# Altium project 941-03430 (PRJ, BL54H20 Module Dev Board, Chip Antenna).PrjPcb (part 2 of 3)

## Sheet CS-DOC-000013317[Debugger_MCU].SchDoc: =BoardTitle +' IMCU'
size OrCAD C; Organization: Nordic Semiconductor; DocumentNumber: 3; SheetNumber: 4; SheetTotal: 8; CompanyName: Nordic Semiconductor; DocumentSize: A4; SheetName: Debugger_MCU
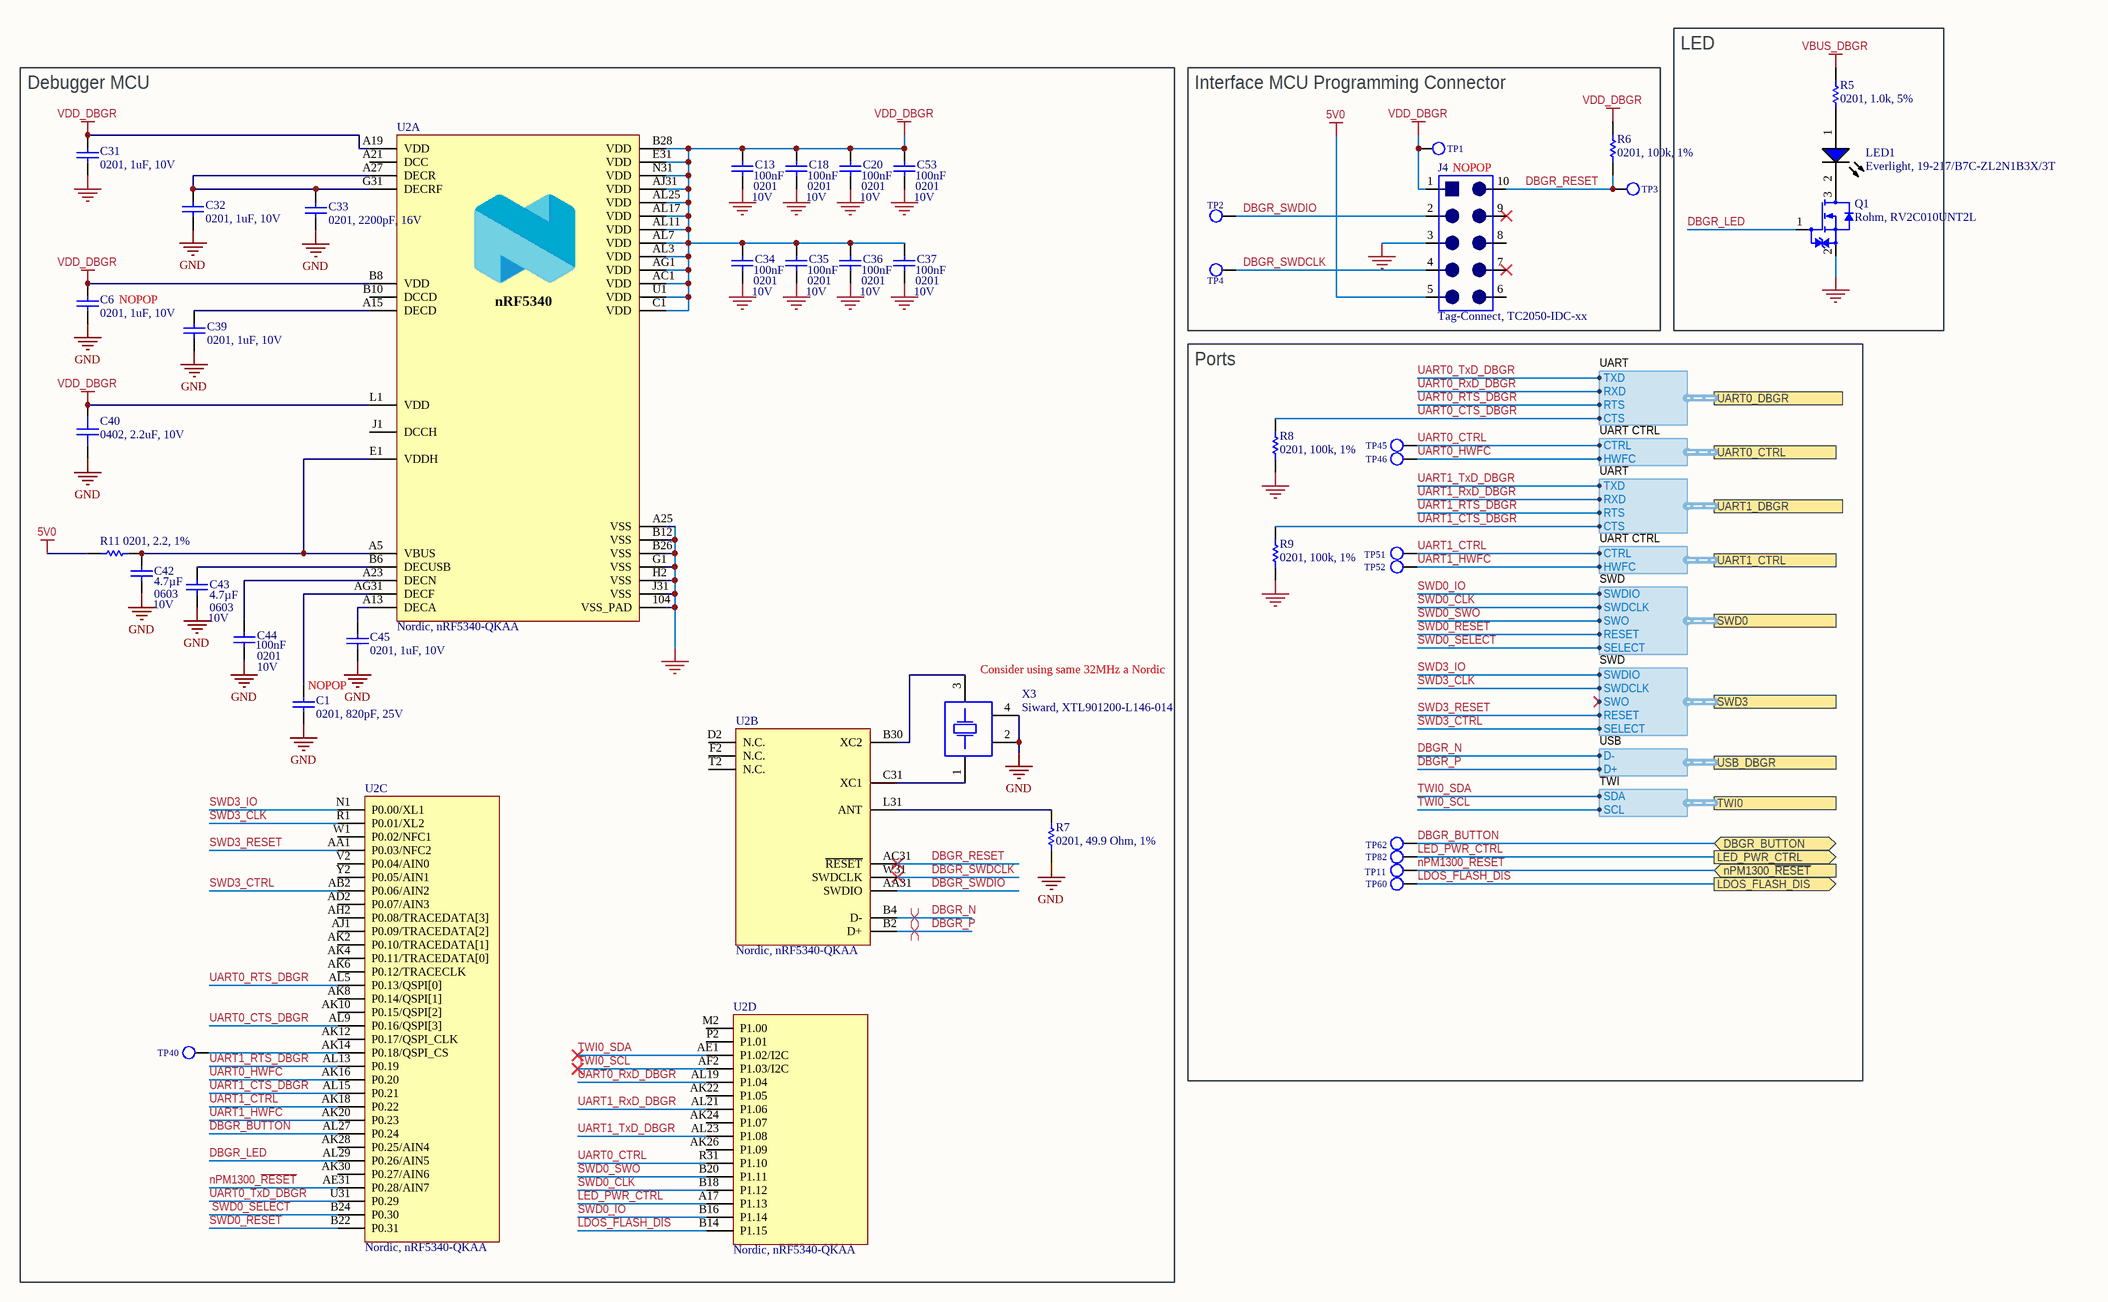
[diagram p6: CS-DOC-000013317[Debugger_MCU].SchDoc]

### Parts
C1  0201, 820pF, 25V  [Cap, C0201, Height 0.3mm]
C6  0201, 1uF, 10V  [Cap, C0201, Height 0.3mm]
C13  value 100nF  Footprint: 0201  Voltage: 10V  [Cap, C0201, Height 0.3mm]  (hidden comment: 0201, 100nF, 10V)
C18  value 100nF  Footprint: 0201  Voltage: 10V  [Cap, C0201, Height 0.3mm]  (hidden comment: 0201, 100nF, 10V)
C20  value 100nF  Footprint: 0201  Voltage: 10V  [Cap, C0201, Height 0.3mm]  (hidden comment: 0201, 100nF, 10V)
C31  0201, 1uF, 10V  [Cap, C0201, Height 0.3mm]
C32  0201, 1uF, 10V  [Cap, C0201, Height 0.3mm]
C33  0201, 2200pF, 16V  [Cap, C0201, Height 0.3mm]
C34  value 100nF  Footprint: 0201  Voltage: 10V  [Cap, C0201, Height 0.3mm]  (hidden comment: 0201, 100nF, 10V)
C35  value 100nF  Footprint: 0201  Voltage: 10V  [Cap, C0201, Height 0.3mm]  (hidden comment: 0201, 100nF, 10V)
C36  value 100nF  Footprint: 0201  Voltage: 10V  [Cap, C0201, Height 0.3mm]  (hidden comment: 0201, 100nF, 10V)
C37  value 100nF  Footprint: 0201  Voltage: 10V  [Cap, C0201, Height 0.3mm]  (hidden comment: 0201, 100nF, 10V)
C39  0201, 1uF, 10V  [Cap, C0201, Height 0.3mm]
C40  0402, 2.2uF, 10V  [Chip. 0402, RF]
C42  value 4.7µF  Footprint: 0603  Voltage: 10V  [Chip, 0603, RF]  (hidden comment: 0603, 4.7µF, 10V)
C43  value 4.7µF  Footprint: 0603  Voltage: 10V  [Chip, 0603, RF]  (hidden comment: 0603, 4.7µF, 10V)
C44  value 100nF  Footprint: 0201  Voltage: 10V  [Cap, C0201, Height 0.3mm]  (hidden comment: 0201, 100nF, 10V)
C45  0201, 1uF, 10V  [Cap, C0201, Height 0.3mm]
C53  value 100nF  Footprint: 0201  Voltage: 10V  [Cap, C0201, Height 0.3mm]  (hidden comment: 0201, 100nF, 10V)
J4  Tag-Connect, TC2050-IDC-xx  [TC2050-NL, TAG Test Interface]  (no BOM)
LED1  Everlight, 19-217/B7C-ZL2N1B3X/3T  [Everlight, LED0603, Blue]
Q1  Rohm, RV2C010UNT2L  [DFN1006-3]
R5  0201, 1.0k, 5%  [RES, R0201, Height 0.23mm]
R6  0201, 100k, 1%  [RES, R0201, Height 0.23mm]
R7  0201, 49.9 Ohm, 1%  [RES, R0201, Height 0.23mm]
R8  0201, 100k, 1%  [RES, R0201, Height 0.23mm]
R9  0201, 100k, 1%  [RES, R0201, Height 0.23mm]
R11  0201, 2.2, 1%  [RES, R0201, Height 0.23mm]
TP1  SMT, 1.5mm, Test Pad  [Test Point, SMT 1.5mm Round]  (value not drawn)  (no BOM)
TP2  SMT, 1.5mm, Test Pad  [Test Point, SMT 1.5mm Round]  (value not drawn)  (no BOM)
TP3  SMT, 1.5mm, Test Pad  [Test Point, SMT 1.5mm Round]  (value not drawn)  (no BOM)
TP4  SMT, 1.5mm, Test Pad  [Test Point, SMT 1.5mm Round]  (value not drawn)  (no BOM)
TP11  SMT, 1.5mm, Test Pad  [Test Point, SMT 1.5mm Round]  (value not drawn)  (no BOM)
TP40  SMT, 1.5mm, Test Pad  [Test Point, SMT 1.5mm Round]  (value not drawn)  (no BOM)
TP45  SMT, 1.5mm, Test Pad  [Test Point, SMT 1.5mm Round]  (value not drawn)  (no BOM)
TP46  SMT, 1.5mm, Test Pad  [Test Point, SMT 1.5mm Round]  (value not drawn)  (no BOM)
TP51  SMT, 1.5mm, Test Pad  [Test Point, SMT 1.5mm Round]  (value not drawn)  (no BOM)
TP52  SMT, 1.5mm, Test Pad  [Test Point, SMT 1.5mm Round]  (value not drawn)  (no BOM)
TP60  SMT, 1.5mm, Test Pad  [Test Point, SMT 1.5mm Round]  (value not drawn)  (no BOM)
TP62  SMT, 1.5mm, Test Pad  [Test Point, SMT 1.5mm Round]  (value not drawn)  (no BOM)
TP82  SMT, 1.5mm, Test Pad  [Test Point, SMT 1.5mm Round]  (value not drawn)  (no BOM)
U2  Nordic, nRF5340-QKAA  [Nordic, nRF5340-QKAA]  (parts A,B,C,D of 4)
X3  Siward, XTL901200-L146-014  [Crystal, 4 pin, 1.6mm x 1.2mm]

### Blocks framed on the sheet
LED: LED1 Q1 R5
Debugger MCU: C1 C6 C13 C18 C20 C31-C37 C39 C40 C42-C45 C53 R7 R11 TP40 U2 X3
Interface MCU Programming Connector: J4 R6 TP1-TP4
Ports: R8 R9 TP11 TP45 TP46 TP51 TP52 TP60 TP62 TP82

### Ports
DBGR_BUTTON (bidir), LDOS_FLASH_DIS (out), LED_PWR_CTRL (out), nPM1300_~{RESET} (in), SWD0 (harness SWD), SWD3 (harness SWD), TWI0 (harness TWI), UART0_CTRL (harness UART CTRL), UART0_DBGR (harness UART), UART1_CTRL (harness UART CTRL), UART1_DBGR (harness UART), USB_DBGR (harness USB)

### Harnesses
SWD: SWDIO, SWDCLK, SWO, RESET, SELECT
UART: RTS, CTS, RXD, TXD
USB: D+, D-
TWI: SCL, SDA
UART CTRL: HWFC, CTRL

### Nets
5V0: J4.5 R11.1
GND: C1.2 C6.2 C13.2 C18.2 C20.2 C31.2 C32.2 C33.2 C34.2 C35.2 C36.2 C37.2 C39.2 C40.2 C42.2 C43.2 C44.2 C45.2 C53.2 J4.3 Q1.2(S) R7.2 R8.2 R9.2 U2.104(VSS_PAD) U2.A25(VSS) U2.B12(VSS) U2.B26(VSS) U2.G1(VSS) U2.H2(VSS) U2.J31(VSS) X3.2 X3.4
VBUS_DBGR: R5.2
VDD_DBGR: C6.1 C13.1 C18.1 C20.1 C31.1 C34.1 C35.1 C36.1 C37.1 C40.1 C53.1 J4.1 R6.2 TP1.1 U2.A19(VDD) U2.AC1(VDD) U2.AG1(VDD) U2.AJ31(VDD) U2.AL3(VDD) U2.AL7(VDD) U2.AL11(VDD) U2.AL17(VDD) U2.AL25(VDD) U2.B8(VDD) U2.B28(VDD) U2.C1(VDD) U2.E31(VDD) U2.L1(VDD) U2.N31(VDD) U2.U1(VDD)
DBGR_BUTTON: TP62.1 U2.AL27(P0.24) ; port DBGR_BUTTON
DBGR_LED: Q1.1(G) U2.AL29(P0.26/AIN5)
DBGR_N: U2.B4(D-) ; port USB_DBGR.D-
DBGR_P: U2.B2(D+) ; port USB_DBGR.D+
DBGR_RESET: J4.10 R6.1 TP3.1 U2.AC31(~{RESET})
DBGR_SWDCLK: J4.4 TP4.1 U2.W31(SWDCLK)
DBGR_SWDIO: J4.2 TP2.1 U2.AA31(SWDIO)
LDOS_FLASH_DIS: TP60.1 U2.B14(P1.15) ; port LDOS_FLASH_DIS
LED_PWR_CTRL: TP82.1 U2.A17(P1.13) ; port LED_PWR_CTRL
nPM1300_~{RESET}: TP11.1 U2.AE31(P0.28/AIN7) ; port nPM1300_~{RESET}
SWD0_CLK: U2.B18(P1.12) ; port SWD0.SWDCLK
SWD0_IO: U2.B16(P1.14) ; port SWD0.SWDIO
SWD0_RESET: U2.B22(P0.31) ; port SWD0.RESET
SWD0_SELECT: U2.B24(P0.30) ; port SWD0.SELECT
SWD0_SWO: U2.B20(P1.11) ; port SWD0.SWO
SWD3_CLK: U2.R1(P0.01/XL2) ; port SWD3.SWDCLK
SWD3_CTRL: U2.AB2(P0.06/AIN2) ; port SWD3.SELECT
SWD3_IO: U2.N1(P0.00/XL1) ; port SWD3.SWDIO
SWD3_RESET: U2.AA1(P0.03/NFC2) ; port SWD3.RESET
TWI0_SCL: U2.AF2(P1.03/I2C) ; port TWI0.SCL
TWI0_SDA: U2.AE1(P1.02/I2C) ; port TWI0.SDA
UART0_CTRL: TP45.1 U2.R31(P1.10) ; port UART0_CTRL.CTRL
UART0_CTS_DBGR: R8.1 U2.AL9(P0.16/QSPI[3]) ; port UART0_DBGR.CTS
UART0_HWFC: TP46.1 U2.AK16(P0.20) ; port UART0_CTRL.HWFC
UART0_RTS_DBGR: U2.AL5(P0.13/QSPI[0]) ; port UART0_DBGR.RTS
UART0_RxD_DBGR: U2.AL19(P1.04) ; port UART0_DBGR.RXD
UART0_TxD_DBGR: U2.U31(P0.29) ; port UART0_DBGR.TXD
UART1_CTRL: TP51.1 U2.AK18(P0.22) ; port UART1_CTRL.CTRL
UART1_CTS_DBGR: R9.1 U2.AL15(P0.21) ; port UART1_DBGR.CTS
UART1_HWFC: TP52.1 U2.AK20(P0.23) ; port UART1_CTRL.HWFC
UART1_RTS_DBGR: U2.AL13(P0.19) ; port UART1_DBGR.RTS
UART1_RxD_DBGR: U2.AL21(P1.06) ; port UART1_DBGR.RXD
UART1_TxD_DBGR: U2.AL23(P1.08) ; port UART1_DBGR.TXD
NetC1_1: C1.1 U2.AG31(DECF)
NetC32_1: C32.1 C33.1 U2.A27(DECR) U2.G31(DECRF)
NetC39_1: C39.1 U2.A15(DECD)
NetC42_1: C42.1 R11.2 U2.A5(VBUS) U2.E1(VDDH)
NetC43_1: C43.1 U2.B6(DECUSB)
NetC44_1: C44.1 U2.A23(DECN)
NetC45_1: C45.1 U2.A13(DECA)
NetLED1_1: LED1.1(A) R5.1
NetLED1_2: LED1.2(K) Q1.3(D)
NetR7_1: R7.1 U2.L31(ANT)
NetTP40_1: TP40.1 U2.AK14(P0.18/QSPI_CS)
NetU2_B30: U2.B30(XC2) X3.3
NetU2_C31: U2.C31(XC1) X3.1

Not connected (* = marked no-connect by the designer): J4 6 7* 8 9*; U2 A21(DCC) AD2(P0.07/AIN3) AH2(P0.08/TRACEDATA[3]) AJ1(P0.09/TRACEDATA[2]) AK2(P0.10/TRACEDATA[1]) AK4(P0.11/TRACEDATA[0]) AK6(P0.12/TRACECLK) AK8(P0.14/QSPI[1]) AK10(P0.15/QSPI[2]) AK12(P0.17/QSPI_CLK) AK22(P1.05) AK24(P1.07) AK26(P1.09) AK28(P0.25/AIN4) AK30(P0.27/AIN6) B10(DCCD) D2(N.C.) F2(N.C.) J1(DCCH) M2(P1.00) P2(P1.01) T2(N.C.) V2(P0.04/AIN0) W1(P0.02/NFC1) Y2(P0.05/AIN1)

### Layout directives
differential pair; differential pair class IMCU; net class USB: DBGR_N, DBGR_P

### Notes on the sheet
- (near J4) NOPOP
- NOPOP
- (near C1) NOPOP
- (near X3) Consider using same 32MHz a Nordic

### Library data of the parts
C1 = CMP-CAP-502-00099-1.10: CAP, SMT, 0201, MLCC, 820pF, 25V, C0G, NP0, 5%; Manufacturer: Murata; Manufacturer Part Number: GRM0335C1E821JA01#; Substitutes Allowed: NO
C6 C31 C32 C39 C45 = CMP-CAP-502-00167-1.9: CAP, SMT, 0201, MLCC, 1uF, 10V, X6S, 20%; Manufacturer: Murata; Manufacturer Part Number: GRM033C81A105ME05#; Substitutes Allowed: NO
C13 C18 C20 C34-C37 C44 C53 = CMP-CAP-502-00106-1.11: CAP, SMT, 0201, MLCC, 100nF, 10V, X7S, 10%; Manufacturer Part Number: GRM033C71A104KE14#; Manufacturer: Murata; Substitutes Allowed: NO
C33 = CMP-CAP-502-00155-1.9: CAP, SMT, 0201, MLCC, 2200pF, 16V, X7R, 10%; Manufacturer Part Number: GRM033R71C222KA88#; Manufacturer: Murata; Substitutes Allowed: NO
C40 = CMP-CAP-502-00198-1.11: CAP, SMT, 0402, MLCC, 2.2uF, 10V, X7S, 10%; Manufacturer: Murata; Manufacturer Part Number: GRM155C71A225KE11#; Substitutes Allowed: NO
C42 C43 = CMP-CAP-502-00098-1.10: CAP, SMT, 0603, MLCC, 4.7µF, 10V, X7S, 10%; Manufacturer: Murata; Manufacturer Part Number: GRM188C71A475KE11#; Substitutes Allowed: NO
J4 = CMP-CON-130-00027-1.6: CON, SMT/TH, Tag-Connect 2050, ,2 x5 , 3.175mm, PCB Footprint only; Value: TC2050-IDC-NL; Substitutes Allowed: NO
LED1 = CMP-LED-521-00008-1.9: LED, SMT, 0603, Blue, 2.7V, 10mA, 36mcd, 120 deg.; Alt. Manufacturer Part Number: 19-217/BHC-ZL1M2TY/3T; Brightness: 36.0mcd; Substitutes Allowed: YES
Q1 = CMP-FET-506-00027-1.2: FET, SMT, DFN1006-3, N-Channel, 20V, 1A, 470 mOhm, 1Vgs max; Power Max (W): 400mW; Substitutes Allowed: NO; Vgs On: 1V
R5 = CMP-RES-514-00172-1.8: RES, SMT, 0201, Thick Film, 1.0k, 5%, 0.05W; Alt. Manufacturer Part Number: Any; Manufacturer Part Number: RC0201JR-071KL; Manufacturer: YAGEO; Substitutes Allowed: YES
R6 = CMP-RES-514-00064-1.24: RES, SMT, 0201, Thick Film, 100k, 1%, 0.05W; Alt. Manufacturer: Any; Manufacturer Part Number: RC0201FR-07100KL; Manufacturer: Yageo; Substitutes Allowed: YES
R7 = CMP-RES-514-00108-1.13: RES, SMT, 0201, Thick Film, 49.9, 1%, 0.05W; Manufacturer Part Number: RC0201FR-0749R9L; Alt. Manufacturer Part Number: Any; Manufacturer: Yageo; Value: 49.9; Substitutes Allowed: YES
R8 R9 = CMP-RES-514-00064-1.24: RES, SMT, 0201, Thick Film, 100k, 1%, 0.05W; Manufacturer Part Number: RC0201FR-07100KL; Alt. Manufacturer Part Number: Any; Manufacturer: Yageo; Substitutes Allowed: YES
R11 = CMP-RES-514-00319-1.1: RES, SMT, 0201, Thick Film, 2.2, 1%, 0.05W; Alt. Manufacturer: Any; Manufacturer: Yageo; Manufacturer Part Number: RC0201FR-072R2L; Substitutes Allowed: YES; Value: 2.2
TP1-TP4 TP11 TP40 TP45 TP46 TP51 TP52 TP60 TP62 TP82 = CMP-MSC-522-00070-1.0: MSC, SMT, 1.5mm, Test Pad
U2 = CMP-IC-510-00161-1.5: IC, SMT, aQFN-94(7x7), Multi-protocol Bluetooth Low Energy, IEEE 802.15.4, ANT and 2.4GHz proprietary system-on-chip; Manufacturer: Nordic Semiconductor; Subpart Type: RF Transceiver; Substitutes Allowed: NO; Supply Voltage: 1.7V~5.5V; Supply Current: 80mA
X3 = CMP-XTL-524-00010-1.5: XTL, SMT, 4 pin, 1.2mm x 1.6mm, 32MHz, 15ppm, 60 Ohm, 8pF; Subpart Type: AT-Cut; ESR: 60 Ohm; Frequency: 32.000000MHz; Substitutes Allowed: NO; Value: 32.000000MHz

## Sheet CS-DOC-000013317[Level_Shifters].SchDoc: =BoardTitle +' Level Shifters'
size OrCAD C; Organization: Nordic Semiconductor; DocumentNumber: 4; SheetNumber: 5; SheetTotal: 8; CompanyName: Nordic Semiconductor; DocumentSize: A4; SheetName: Level_Shifters
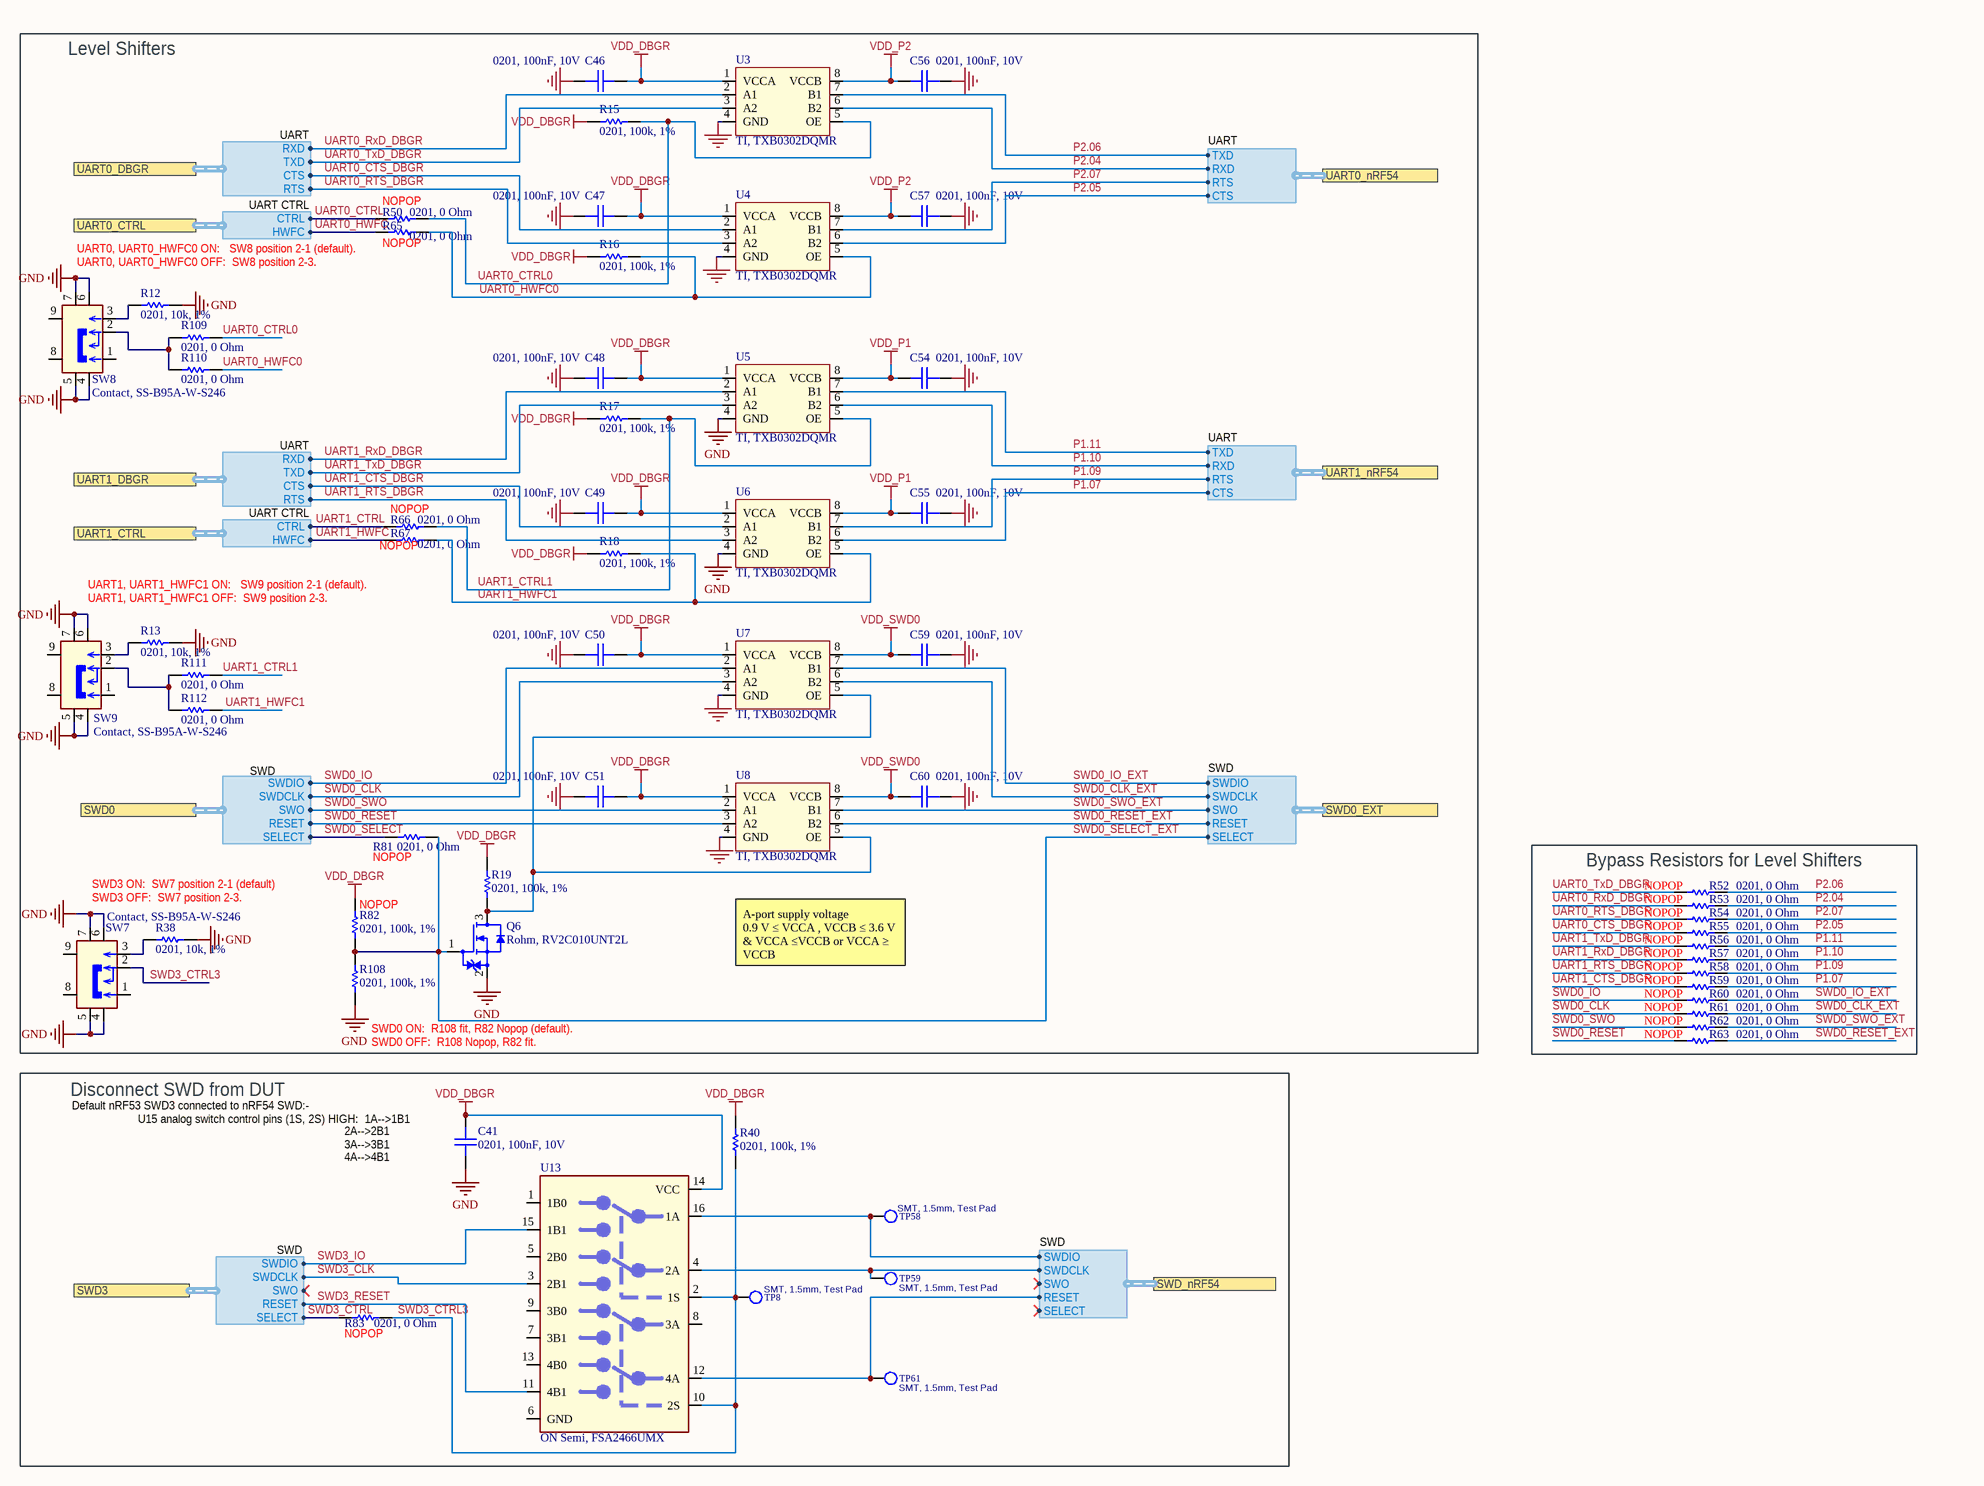
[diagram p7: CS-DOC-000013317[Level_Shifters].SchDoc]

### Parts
C41  0201, 100nF, 10V  [Cap, C0201, Height 0.3mm]
C46  0201, 100nF, 10V  [Cap, C0201, Height 0.3mm]
C47  0201, 100nF, 10V  [Cap, C0201, Height 0.3mm]
C48  0201, 100nF, 10V  [Cap, C0201, Height 0.3mm]
C49  0201, 100nF, 10V  [Cap, C0201, Height 0.3mm]
C50  0201, 100nF, 10V  [Cap, C0201, Height 0.3mm]
C51  0201, 100nF, 10V  [Cap, C0201, Height 0.3mm]
C54  0201, 100nF, 10V  [Cap, C0201, Height 0.3mm]
C55  0201, 100nF, 10V  [Cap, C0201, Height 0.3mm]
C56  0201, 100nF, 10V  [Cap, C0201, Height 0.3mm]
C57  0201, 100nF, 10V  [Cap, C0201, Height 0.3mm]
C59  0201, 100nF, 10V  [Cap, C0201, Height 0.3mm]
C60  0201, 100nF, 10V  [Cap, C0201, Height 0.3mm]
Q6  Rohm, RV2C010UNT2L  [DFN1006-3]
R12  0201, 10k, 1%  [RES, R0201, Height 0.23mm]
R13  0201, 10k, 1%  [RES, R0201, Height 0.23mm]
R15  0201, 100k, 1%  [RES, R0201, Height 0.23mm]
R16  0201, 100k, 1%  [RES, R0201, Height 0.23mm]
R17  0201, 100k, 1%  [RES, R0201, Height 0.23mm]
R18  0201, 100k, 1%  [RES, R0201, Height 0.23mm]
R19  0201, 100k, 1%  [RES, R0201, Height 0.23mm]
R38  0201, 10k, 1%  [RES, R0201, Height 0.23mm]
R40  0201, 100k, 1%  [RES, R0201, Height 0.23mm]
R50  0201, 0 Ohm  [RES, R0201, Height 0.23mm]
R52  0201, 0 Ohm  [RES, R0201, Height 0.23mm]
R53  0201, 0 Ohm  [RES, R0201, Height 0.23mm]
R54  0201, 0 Ohm  [RES, R0201, Height 0.23mm]
R55  0201, 0 Ohm  [RES, R0201, Height 0.23mm]
R56  0201, 0 Ohm  [RES, R0201, Height 0.23mm]
R57  0201, 0 Ohm  [RES, R0201, Height 0.23mm]
R58  0201, 0 Ohm  [RES, R0201, Height 0.23mm]
R59  0201, 0 Ohm  [RES, R0201, Height 0.23mm]
R60  0201, 0 Ohm  [RES, R0201, Height 0.23mm]
R61  0201, 0 Ohm  [RES, R0201, Height 0.23mm]
R62  0201, 0 Ohm  [RES, R0201, Height 0.23mm]
R63  0201, 0 Ohm  [RES, R0201, Height 0.23mm]
R65  0201, 0 Ohm  [RES, R0201, Height 0.23mm]
R66  0201, 0 Ohm  [RES, R0201, Height 0.23mm]
R67  0201, 0 Ohm  [RES, R0201, Height 0.23mm]
R81  0201, 0 Ohm  [RES, R0201, Height 0.23mm]
R82  0201, 100k, 1%  [RES, R0201, Height 0.23mm]
R83  0201, 0 Ohm  [RES, R0201, Height 0.23mm]
R108  0201, 100k, 1%  [RES, R0201, Height 0.23mm]
R109  0201, 0 Ohm  [RES, R0201, Height 0.23mm]
R110  0201, 0 Ohm  [RES, R0201, Height 0.23mm]
R111  0201, 0 Ohm  [RES, R0201, Height 0.23mm]
R112  0201, 0 Ohm  [RES, R0201, Height 0.23mm]
SW7  Contact, SS-B95A-W-S246  [Contact, SS-B95A-W-S246]
SW8  Contact, SS-B95A-W-S246  [Contact, SS-B95A-W-S246]
SW9  Contact, SS-B95A-W-S246  [Contact, SS-B95A-W-S246]
TP8  SMT, 1.5mm, Test Pad  [Test Point, SMT 1.5mm Round]  (no BOM)
TP58  SMT, 1.5mm, Test Pad  [Test Point, SMT 1.5mm Round]  (no BOM)
TP59  SMT, 1.5mm, Test Pad  [Test Point, SMT 1.5mm Round]  (no BOM)
TP61  SMT, 1.5mm, Test Pad  [Test Point, SMT 1.5mm Round]  (no BOM)
U3  TI, TXB0302DQMR  [X2SON, 8-Leads, SMD]
U4  TI, TXB0302DQMR  [X2SON, 8-Leads, SMD]
U5  TI, TXB0302DQMR  [X2SON, 8-Leads, SMD]
U6  TI, TXB0302DQMR  [X2SON, 8-Leads, SMD]
U7  TI, TXB0302DQMR  [X2SON, 8-Leads, SMD]
U8  TI, TXB0302DQMR  [X2SON, 8-Leads, SMD]
U13  ON Semi, FSA2466UMX  [UQFN16, 2.6x1.8, Pitch 0.4mm, Height 0.5mm]

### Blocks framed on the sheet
Level Shifters: C46-C51 C54-C57 C59 C60 Q6 R12 R13 R15-R19 R38 R50 R65-R67 R81 R82 R108-R112 SW7-SW9 U3-U8
Bypass Resistors for Level Shifters: R52-R63
Disconnect SWD from DUT: C41 R40 R83 TP8 TP58 TP59 TP61 U13

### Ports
SWD0 (harness SWD), SWD0_EXT (harness SWD), SWD3 (harness SWD), SWD_nRF54 (harness SWD), UART0_CTRL (harness UART CTRL), UART0_DBGR (harness UART), UART0_nRF54 (harness UART), UART1_CTRL (harness UART CTRL), UART1_DBGR (harness UART), UART1_nRF54 (harness UART)

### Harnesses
SWD: SWDIO, SWDCLK, SWO, RESET, SELECT
UART: RTS, CTS, RXD, TXD
UART CTRL: HWFC, CTRL

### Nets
GND: C41.2 C46.1 C47.1 C48.1 C49.1 C50.1 C51.1 C54.1 C55.1 C56.1 C57.1 C59.1 C60.1 Q6.2(S) R12.2 R13.2 R38.2 R108.2 SW7.4 SW7.5 SW7.6 SW7.7 SW8.4 SW8.5 SW8.6 SW8.7 SW9.4 SW9.5 SW9.6 SW9.7 U3.4(GND) U4.4(GND) U5.4(GND) U6.4(GND) U7.4(GND) U8.4(GND)
VDD_DBGR: C41.1 C46.2 C47.2 C48.2 C49.2 C50.2 C51.2 R15.1 R16.1 R17.1 R18.1 R19.2 R40.1 R82.1 U3.1(VCCA) U4.1(VCCA) U5.1(VCCA) U6.1(VCCA) U7.1(VCCA) U8.1(VCCA) U13.14(VCC)
VDD_P1: C54.2 C55.2 U5.8(VCCB) U6.8(VCCB)
VDD_P2: C56.2 C57.2 U3.8(VCCB) U4.8(VCCB)
VDD_SWD0: C59.2 C60.2 U7.8(VCCB) U8.8(VCCB)
nRF54H20_RESET: TP61.1 U13.12(4A) ; port SWD_nRF54.RESET
P1.07: R59.1 U6.6(B2) ; port UART1_nRF54.CTS
P1.09: R58.1 U6.7(B1) ; port UART1_nRF54.RTS
P1.10: R57.1 U5.6(B2) ; port UART1_nRF54.RXD
P1.11: R56.1 U5.7(B1) ; port UART1_nRF54.TXD
P2.04: R53.1 U3.6(B2) ; port UART0_nRF54.RXD
P2.05: R55.1 U4.6(B2) ; port UART0_nRF54.CTS
P2.06: R52.1 U3.7(B1) ; port UART0_nRF54.TXD
P2.07: R54.1 U4.7(B1) ; port UART0_nRF54.RTS
SWD0_CLK: R61.2 U7.3(A2) ; port SWD0.SWDCLK
SWD0_CLK_EXT: R61.1 U7.6(B2) ; port SWD0_EXT.SWDCLK
SWD0_IO: R60.2 U7.2(A1) ; port SWD0.SWDIO
SWD0_IO_EXT: R60.1 U7.7(B1) ; port SWD0_EXT.SWDIO
SWD0_RESET: R63.2 U8.3(A2) ; port SWD0.RESET
SWD0_RESET_EXT: R63.1 U8.6(B2) ; port SWD0_EXT.RESET
SWD0_SELECT: R81.1 ; port SWD0.SELECT
SWD0_SELECT_EXT: Q6.1(G) R81.2 R82.2 R108.1 ; port SWD0_EXT.SELECT
SWD0_SWO: R62.2 U8.2(A1) ; port SWD0.SWO
SWD0_SWO_EXT: R62.1 U8.7(B1) ; port SWD0_EXT.SWO
SWD3_CLK: U13.3(2B1) ; port SWD3.SWDCLK
SWD3_CTRL: R83.1 ; port SWD3.SELECT
SWD3_CTRL3: R40.2 R83.2 SW7.2 TP8.1 U13.2(1S) U13.10(2S)
SWD3_IO: U13.15(1B1) ; port SWD3.SWDIO
SWD3_RESET: U13.11(4B1) ; port SWD3.RESET
SWDCLK: TP59.1 U13.4(2A) ; port SWD_nRF54.SWDCLK
SWDIO: TP58.1 U13.16(1A) ; port SWD_nRF54.SWDIO
UART0_CTRL: R50.1 ; port UART0_CTRL.CTRL
UART0_CTRL0: R15.2 R50.2 R109.2 U3.5(OE)
UART0_CTS_DBGR: R55.2 U4.2(A1) ; port UART0_DBGR.CTS
UART0_HWFC: R65.1 ; port UART0_CTRL.HWFC
UART0_HWFC0: R16.2 R65.2 R110.2 U4.5(OE)
UART0_RTS_DBGR: R54.2 U4.3(A2) ; port UART0_DBGR.RTS
UART0_RxD_DBGR: R53.2 U3.2(A1) ; port UART0_DBGR.RXD
UART0_TxD_DBGR: R52.2 U3.3(A2) ; port UART0_DBGR.TXD
UART1_CTRL: R66.1 ; port UART1_CTRL.CTRL
UART1_CTRL1: R17.2 R66.2 R111.2 U5.5(OE)
UART1_CTS_DBGR: R59.2 U6.2(A1) ; port UART1_DBGR.CTS
UART1_HWFC: R67.1 ; port UART1_CTRL.HWFC
UART1_HWFC1: R18.2 R67.2 R112.2 U6.5(OE)
UART1_RTS_DBGR: R58.2 U6.3(A2) ; port UART1_DBGR.RTS
UART1_RxD_DBGR: R57.2 U5.2(A1) ; port UART1_DBGR.RXD
UART1_TxD_DBGR: R56.2 U5.3(A2) ; port UART1_DBGR.TXD
NetQ6_3: Q6.3(D) R19.1 U7.5(OE) U8.5(OE)
NetR12_1: R12.1 SW8.3
NetR13_1: R13.1 SW9.3
NetR38_1: R38.1 SW7.3
NetR109_1: R109.1 R110.1 SW8.2
NetR111_1: R111.1 R112.1 SW9.2

Not connected (* = marked no-connect by the designer): SW7 1 8 9; SW8 1 8 9; SW9 1 8 9; U13 1(1B0) 5(2B0) 6(GND) 7(3B1) 8(3A) 9(3B0) 13(4B0)

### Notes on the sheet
- UART0, UART0_HWFC0 OFF:  SW8 position 2-3.
- (near R65) UART0, UART0_HWFC0 ON:   SW8 position 2-1 (default).
- (near R50) NOPOP
- (near R65) NOPOP
- (near R66) NOPOP
- UART1, UART1_HWFC1 OFF:  SW9 position 2-3.
- UART1, UART1_HWFC1 ON:   SW9 position 2-1 (default).
- (near R67) NOPOP
- (near R81) NOPOP
- SWD3 OFF:  SW7 position 2-3.
- SWD3 ON:  SW7 position 2-1 (default)
- (near R82) NOPOP
- NOPOP
- A-port supply voltage
  0.9 V ≤ VCCA , VCCB ≤ 3.6 V
  & VCCA ≤VCCB or VCCA ≥ VCCB
- SWD0 OFF:  R108 Nopop, R82 fit.
- (near R108) SWD0 ON:  R108 fit, R82 Nopop (default).
- Default nRF53 SWD3 connected to nRF54 SWD:-
- (near C41) U15 analog switch control pins (1S, 2S) HIGH:  1A-->1B1
- 2A-->2B1
- 3A-->3B1
- 4A-->4B1
- (near R83) NOPOP

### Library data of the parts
C41 C46-C51 C54-C57 C59 C60 = CMP-CAP-502-00106-1.11: CAP, SMT, 0201, MLCC, 100nF, 10V, X7S, 10%; Manufacturer: Murata; Manufacturer Part Number: GRM033C71A104KE14#; Substitutes Allowed: NO
Q6 = CMP-FET-506-00027-1.2: FET, SMT, DFN1006-3, N-Channel, 20V, 1A, 470 mOhm, 1Vgs max; Power Max (W): 400mW; Vgs On: 1V; Substitutes Allowed: NO
R12 R13 R38 = CMP-RES-514-00247-1.2: RES, SMT, 0201, Thick Film, 10k, 1%, 0.05W; Alt. Manufacturer Part Number: Any; Manufacturer Part Number: RC0201FR-7D10KL; Manufacturer: Yageo; Substitutes Allowed: YES
R15-R19 R40 R82 R108 = CMP-RES-514-00064-1.24: as R8 on sheet CS-DOC-000013317[Debugger_MCU]
R50 R65-R67 R81 R83 R109-R112 = CMP-RES-514-00004-1.31: RES, SMT, 0201, Thick Film, 0, 0.05W; Manufacturer: Yageo; Alt. Manufacturer Part Number: Any; Manufacturer Part Number: RC0201JR-070RL; Substitutes Allowed: YES; Tolerance: NA; Value: 0
R52-R63 = CMP-RES-514-00004-1.31: RES, SMT, 0201, Thick Film, 0, 0.05W; Manufacturer: Yageo; Alt. Manufacturer: Any; Manufacturer Part Number: RC0201JR-070RL; Tolerance: NA; Substitutes Allowed: YES; Value: 0
SW7-SW9 = CMP-SW-516-00015-1.3: SW, SMD, Slide, 1P2T, 4VDC, 0.3A; Switch Function: (On, Off, Mom); Substitutes Allowed: NO; Voltage Rating AC/DC: 4V
TP8 TP58 TP59 TP61 = CMP-MSC-522-00070-1.0: MSC, SMT, 1.5mm, Test Pad
U3-U8 = CMP-IC-510-00382-1.0: IC, SMT, X2SON-8, 2-Bit Bidirectional Voltage-Level Translator with Automatic Direction Sensing, 0.9V~3.6V; Subpart Type: Translation Voltage Levels; Manufacturer: Texas Instruments; Substitutes Allowed: NO
U13 = CMP-IC-510-00070-1.1: IC, SMT, UQFN16, Data / Audio Low-Voltage dual DPDT analog switch, 1.65~4.45V, -40C~85C; Manufacturer: ON Semi; Subpart Type: Analog Switch ICs; Supply Voltage: 1.65V~4.45V; Substitutes Allowed: NO

## Sheet CS-DOC-000013317[Misc].SchDoc: =BoardTitle +' Misc'
size OrCAD C; Organization: Nordic Semiconductor; DocumentNumber: 5; SheetNumber: 6; SheetTotal: 8; CompanyName: Nordic Semiconductor; DocumentSize: A4; SheetName: Misc
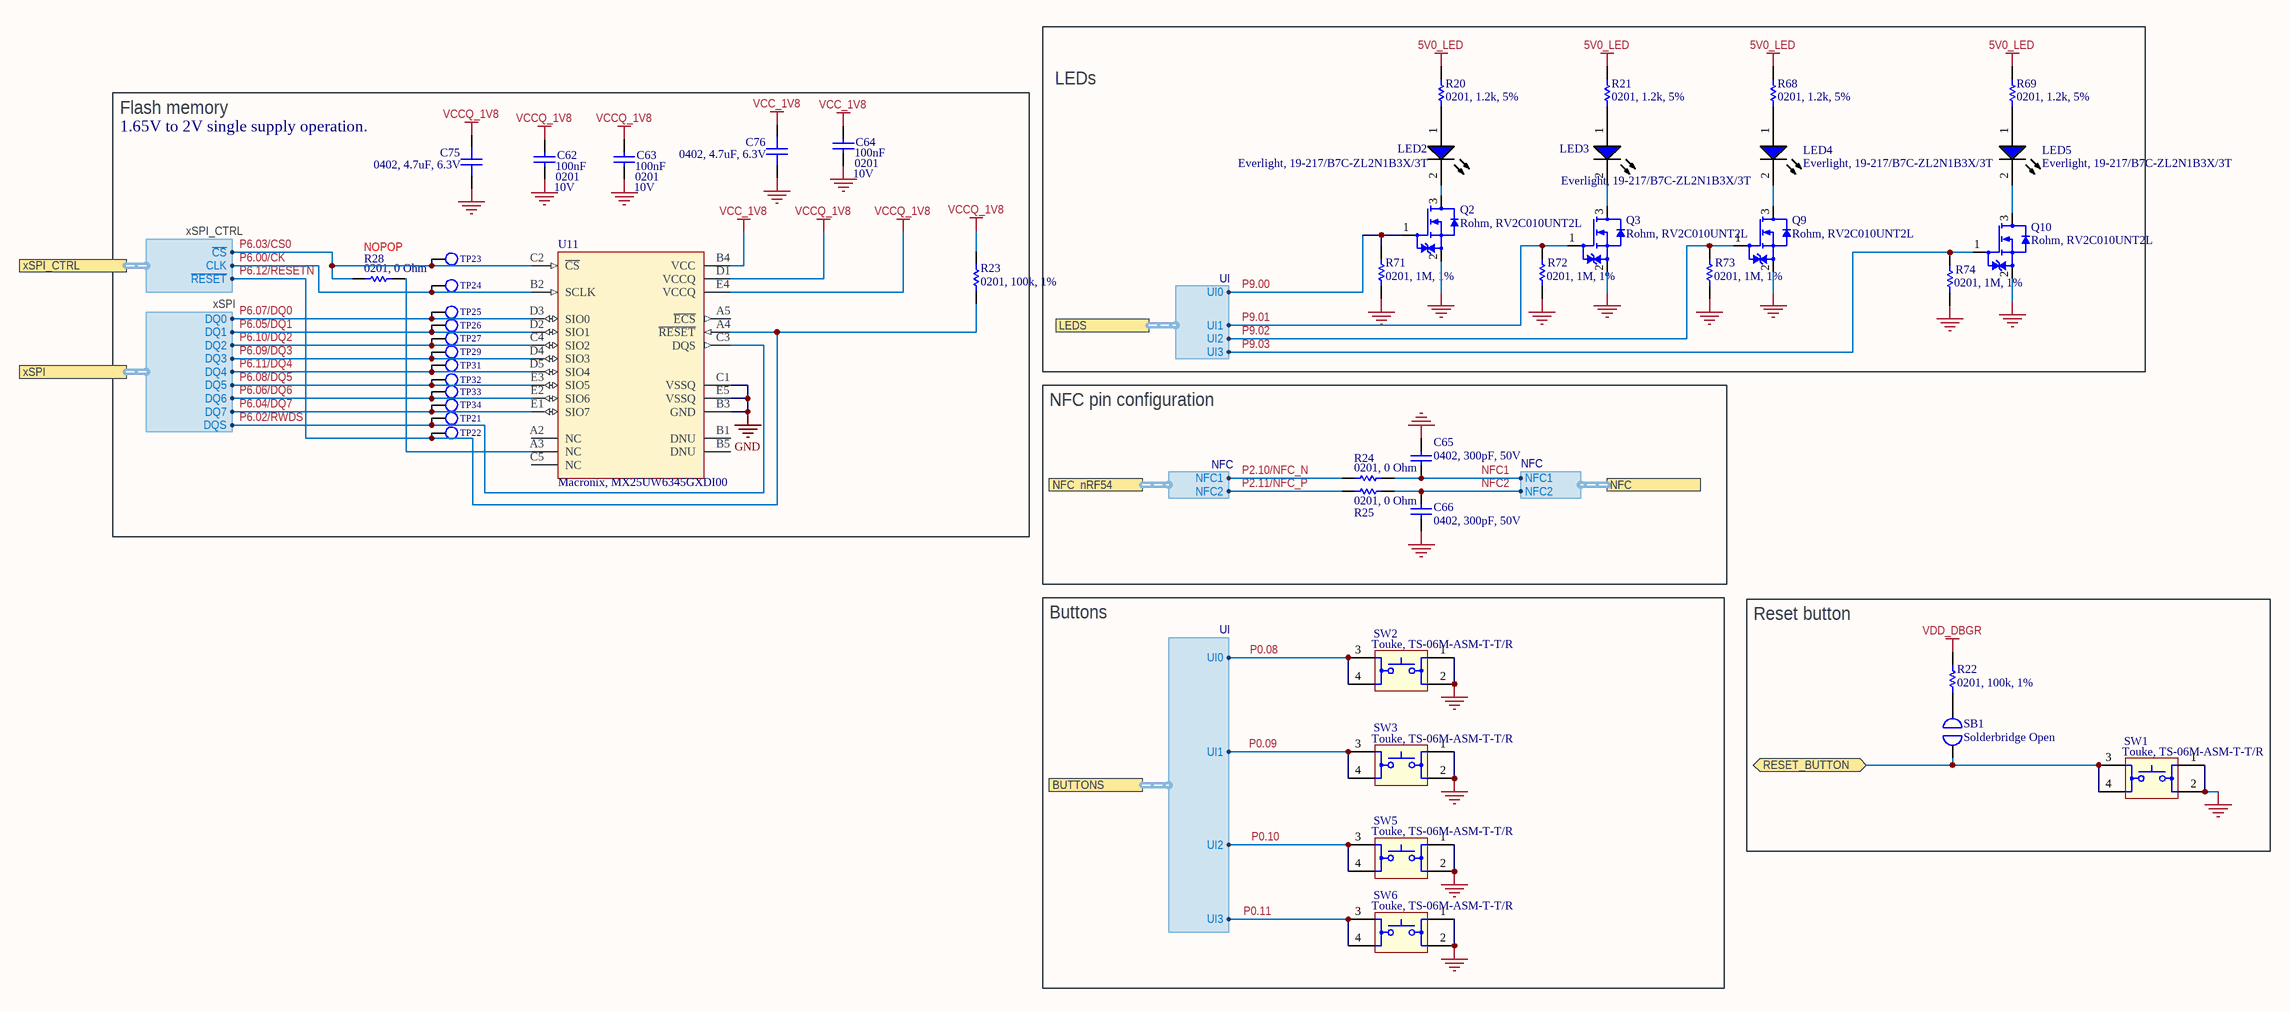
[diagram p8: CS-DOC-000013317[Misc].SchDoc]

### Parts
C62  value 100nF  Footprint: 0201  Voltage: 10V  [Cap, C0201, Height 0.3mm]  (hidden comment: 0201, 100nF, 10V)
C63  value 100nF  Footprint: 0201  Voltage: 10V  [Cap, C0201, Height 0.3mm]  (hidden comment: 0201, 100nF, 10V)
C64  value 100nF  Footprint: 0201  Voltage: 10V  [Cap, C0201, Height 0.3mm]  (hidden comment: 0201, 100nF, 10V)
C65  0402, 300pF, 50V  [Chip. 0402, RF]
C66  0402, 300pF, 50V  [Chip. 0402, RF]
C75  0402, 4.7uF, 6.3V  [Chip. 0402, RF]
C76  0402, 4.7uF, 6.3V  [Chip. 0402, RF]
LED2  Everlight, 19-217/B7C-ZL2N1B3X/3T  [Everlight, LED0603, Blue]
LED3  Everlight, 19-217/B7C-ZL2N1B3X/3T  [Everlight, LED0603, Blue]
LED4  Everlight, 19-217/B7C-ZL2N1B3X/3T  [Everlight, LED0603, Blue]
LED5  Everlight, 19-217/B7C-ZL2N1B3X/3T  [Everlight, LED0603, Blue]
Q2  Rohm, RV2C010UNT2L  [DFN1006-3]
Q3  Rohm, RV2C010UNT2L  [DFN1006-3]
Q9  Rohm, RV2C010UNT2L  [DFN1006-3]
Q10  Rohm, RV2C010UNT2L  [DFN1006-3]
R20  0201, 1.2k, 5%  [RES, R0201, Height 0.23mm]
R21  0201, 1.2k, 5%  [RES, R0201, Height 0.23mm]
R22  0201, 100k, 1%  [RES, R0201, Height 0.23mm]
R23  0201, 100k, 1%  [RES, R0201, Height 0.23mm]
R24  0201, 0 Ohm  [RES, R0201, Height 0.23mm]
R25  0201, 0 Ohm  [RES, R0201, Height 0.23mm]
R28  0201, 0 Ohm  [RES, R0201, Height 0.23mm]
R68  0201, 1.2k, 5%  [RES, R0201, Height 0.23mm]
R69  0201, 1.2k, 5%  [RES, R0201, Height 0.23mm]
R71  0201, 1M, 1%  [RES, R0201, Height 0.23mm]
R72  0201, 1M, 1%  [RES, R0201, Height 0.23mm]
R73  0201, 1M, 1%  [RES, R0201, Height 0.23mm]
R74  0201, 1M, 1%  [RES, R0201, Height 0.23mm]
SB1  Solderbridge Open  [Solder Bridge Open]  (no BOM)
SW1  Touke, TS-06M-ASM-T-T/R  [Touke, TS-06M-ASM-T]
SW2  Touke, TS-06M-ASM-T-T/R  [Touke, TS-06M-ASM-T]
SW3  Touke, TS-06M-ASM-T-T/R  [Touke, TS-06M-ASM-T]
SW5  Touke, TS-06M-ASM-T-T/R  [Touke, TS-06M-ASM-T]
SW6  Touke, TS-06M-ASM-T-T/R  [Touke, TS-06M-ASM-T]
TP21  SMT, 0.7mm, Test Pad  [Test Point, SMT 0.7mm Round]  (value not drawn)  (no BOM)
TP22  SMT, 0.7mm, Test Pad  [Test Point, SMT 0.7mm Round]  (value not drawn)  (no BOM)
TP23  SMT, 0.7mm, Test Pad  [Test Point, SMT 0.7mm Round]  (value not drawn)  (no BOM)
TP24  SMT, 0.7mm, Test Pad  [Test Point, SMT 0.7mm Round]  (value not drawn)  (no BOM)
TP25  SMT, 0.7mm, Test Pad  [Test Point, SMT 0.7mm Round]  (value not drawn)  (no BOM)
TP26  SMT, 0.7mm, Test Pad  [Test Point, SMT 0.7mm Round]  (value not drawn)  (no BOM)
TP27  SMT, 0.7mm, Test Pad  [Test Point, SMT 0.7mm Round]  (value not drawn)  (no BOM)
TP29  SMT, 0.7mm, Test Pad  [Test Point, SMT 0.7mm Round]  (value not drawn)  (no BOM)
TP31  SMT, 0.7mm, Test Pad  [Test Point, SMT 0.7mm Round]  (value not drawn)  (no BOM)
TP32  SMT, 0.7mm, Test Pad  [Test Point, SMT 0.7mm Round]  (value not drawn)  (no BOM)
TP33  SMT, 0.7mm, Test Pad  [Test Point, SMT 0.7mm Round]  (value not drawn)  (no BOM)
TP34  SMT, 0.7mm, Test Pad  [Test Point, SMT 0.7mm Round]  (value not drawn)  (no BOM)
U11  Macronix, MX25UW6345GXDI00  [BGA 24, 6mmx8mm, Hight 1.2mm]

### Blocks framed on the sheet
LEDs: LED2-LED5 Q2 Q3 Q9 Q10 R20 R21 R68 R69 R71-R74
Flash memory: C62-C64 C75 C76 R23 R28 TP21-TP27 TP29 TP31-TP34 U11
NFC pin configuration: C65 C66 R24 R25
Buttons: SW2 SW3 SW5 SW6
Reset button: R22 SB1 SW1

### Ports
BUTTONS (harness UI), LEDS (harness UI), NFC (harness NFC), NFC_nRF54 (harness NFC), RESET_BUTTON (bidir), xSPI (harness xSPI), xSPI_CTRL (harness xSPI_CTRL)

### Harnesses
NFC: NFC2, NFC1
UI: UI1, UI0, UI2, UI3
xSPI_CTRL: ~{CS}, CLK, ~{RESET}
xSPI: DQ0, DQ1, DQ2, DQ3, DQ4, DQ5, DQ6, DQ7, DQS

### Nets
5V0_LED: R20.2 R21.2 R68.2 R69.2
GND: C62.2 C63.2 C64.2 C65.2 C66.2 C75.2 C76.2 Q2.2(S) Q3.2(S) Q9.2(S) Q10.2(S) R71.2 R72.2 R73.2 R74.2 SW1.1 SW1.2 SW2.1 SW2.2 SW3.1 SW3.2 SW5.1 SW5.2 SW6.1 SW6.2 U11.B3(GND) U11.C1(VSSQ) U11.E5(VSSQ)
VCC_1V8: C64.1 C76.1 U11.B4(VCC)
VCCQ_1V8: C62.1 C63.1 C75.1 R23.1 U11.D1(VCCQ) U11.E4(VCCQ)
VDD_DBGR: R22.1
NFC1: C65.1 R24.1 ; port NFC.NFC1
NFC2: C66.1 R25.1 ; port NFC.NFC2
P0.08: SW2.3 SW2.4 ; port BUTTONS.UI0
P0.09: SW3.3 SW3.4 ; port BUTTONS.UI1
P0.10: SW5.3 SW5.4 ; port BUTTONS.UI2
P0.11: SW6.3 SW6.4 ; port BUTTONS.UI3
P2.10/NFC_N: R24.2 ; port NFC_nRF54.NFC1
P2.11/NFC_P: R25.2 ; port NFC_nRF54.NFC2
P6.00/CK: TP24.1 U11.B2(SCLK) ; port xSPI_CTRL.CLK
P6.02/RWDS: TP21.1 U11.C3(DQS) ; port xSPI.DQS
P6.03/CS0: R28.2 TP23.1 U11.C2(~{CS}) ; port xSPI_CTRL.~{CS}
P6.04/DQ7: TP34.1 U11.E1(SIO7) ; port xSPI.DQ7
P6.05/DQ1: TP26.1 U11.D2(SIO1) ; port xSPI.DQ1
P6.06/DQ6: TP33.1 U11.E2(SIO6) ; port xSPI.DQ6
P6.07/DQ0: TP25.1 U11.D3(SIO0) ; port xSPI.DQ0
P6.08/DQ5: TP32.1 U11.E3(SIO5) ; port xSPI.DQ5
P6.09/DQ3: TP29.1 U11.D4(SIO3) ; port xSPI.DQ3
P6.10/DQ2: TP27.1 U11.C4(SIO2) ; port xSPI.DQ2
P6.11/DQ4: TP31.1 U11.D5(SIO4) ; port xSPI.DQ4
P6.12/RESETN: R23.2 TP22.1 U11.A4(~{RESET}) ; port xSPI_CTRL.~{RESET}
P9.00: Q2.1(G) R71.1 ; port LEDS.UI0
P9.01: Q3.1(G) R72.1 ; port LEDS.UI1
P9.02: Q9.1(G) R73.1 ; port LEDS.UI2
P9.03: Q10.1(G) R74.1 ; port LEDS.UI3
RESET_BUTTON: SB1.1 SW1.3 SW1.4 ; port RESET_BUTTON
NetLED2_1: LED2.1(A) R20.1
NetLED2_2: LED2.2(K) Q2.3(D)
NetLED3_1: LED3.1(A) R21.1
NetLED3_2: LED3.2(K) Q3.3(D)
NetLED4_1: LED4.1(A) R68.1
NetLED4_2: LED4.2(K) Q9.3(D)
NetLED5_1: LED5.1(A) R69.1
NetLED5_2: LED5.2(K) Q10.3(D)
NetR22_2: R22.2 SB1.2
NetR28_1: R28.1 U11.A3(NC)

Not connected (* = marked no-connect by the designer): U11 A2(NC) A5(~{ECS}) B1(DNU) B5(DNU) C5(NC)

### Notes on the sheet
- (near C75) 1.65V to 2V single supply operation.
- (near R28) NOPOP

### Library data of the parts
C62-C64 = CMP-CAP-502-00106-1.11: as C13 on sheet CS-DOC-000013317[Debugger_MCU]
C65 C66 = CMP-CAP-502-00091-1.17: CAP, SMT, 0402, MLCC, 300pF, 50V, COG/NPO, 5%,; Manufacturer: Walsin; Manufacturer Part Number: 0402N301J500CT; Temp Coefficient: C0G, NP0; Substitutes Allowed: NO
C75 C76 = CMP-CAP-502-00116-1.16: CAP, SMT, 0402, MLCC, 4.7uF, 6.3V, X6S, 20%; Manufacturer: Murata; Manufacturer Part Number: GRM155C80J475MEAA#; Substitutes Allowed: NO
LED2-LED5 = CMP-LED-521-00008-1.9: as LED1 on sheet CS-DOC-000013317[Debugger_MCU]
Q2 Q3 Q9 Q10 = CMP-FET-506-00027-1.2: as Q1 on sheet CS-DOC-000013317[Debugger_MCU]
R20 R21 R68 R69 = CMP-RES-514-00068-1.17: RES, SMT, 0201, Thick Film, 1.2k, 5%, 0.05W; Manufacturer Part Number: RC0201JR-071K2L; Manufacturer: Yageo; Alt. Manufacturer: Any; Substitutes Allowed: YES
R22 R23 = CMP-RES-514-00064-1.24: as R6 on sheet CS-DOC-000013317[Debugger_MCU]
R24 R25 R28 = CMP-RES-514-00004-1.31: as R52-R63 on sheet CS-DOC-000013317[Level_Shifters]
R71-R74 = CMP-RES-514-00017-1.28: RES, SMT, 0201, Thick Film, 1M, 1%, 0.05W; Manufacturer Part Number: RC0201FR-071ML; Manufacturer: Yageo; Alt. Manufacturer: Any; Substitutes Allowed: YES
SB1 = CMP-Misc-522-00003-1.9: MSC, Solderbridge Open
SW1-SW3 SW5 SW6 = CMP-SW-516-00005-1.12: SW, SMT, Tact, Vertical, Momentary On, 6mm x 6mm x 4.3mm; Substitutes Allowed: NO; Voltage Rating AC/DC: 500VAC-1 minute; Switch Circuit: SPST; Switch Function: (On, Off, Mom)
TP21-TP27 TP29 TP31-TP34 = CMP-MSC-522-00071-1.0: MSC, SMT, 0.7mm, Test Pad
U11 = CMP-IC-510-00396-1.1: IC, SMT, TFBGA24, NOR Flash Memory, 64Mb (8M x 8) SPI - Octa I/O, DTR 200MHz, 1.7V~2V; Substitutes Allowed: NO

## Sheet CS-DOC-000013317[Power_Supply].SchDoc: =BoardTitle +' Power Supply GPIO'
size OrCAD C; Organization: Nordic Semiconductor; DocumentNumber: 7; SheetNumber: 7; SheetTotal: 8; CompanyName: Nordic Semiconductor; DocumentSize: A4; SheetName: Power_Supply
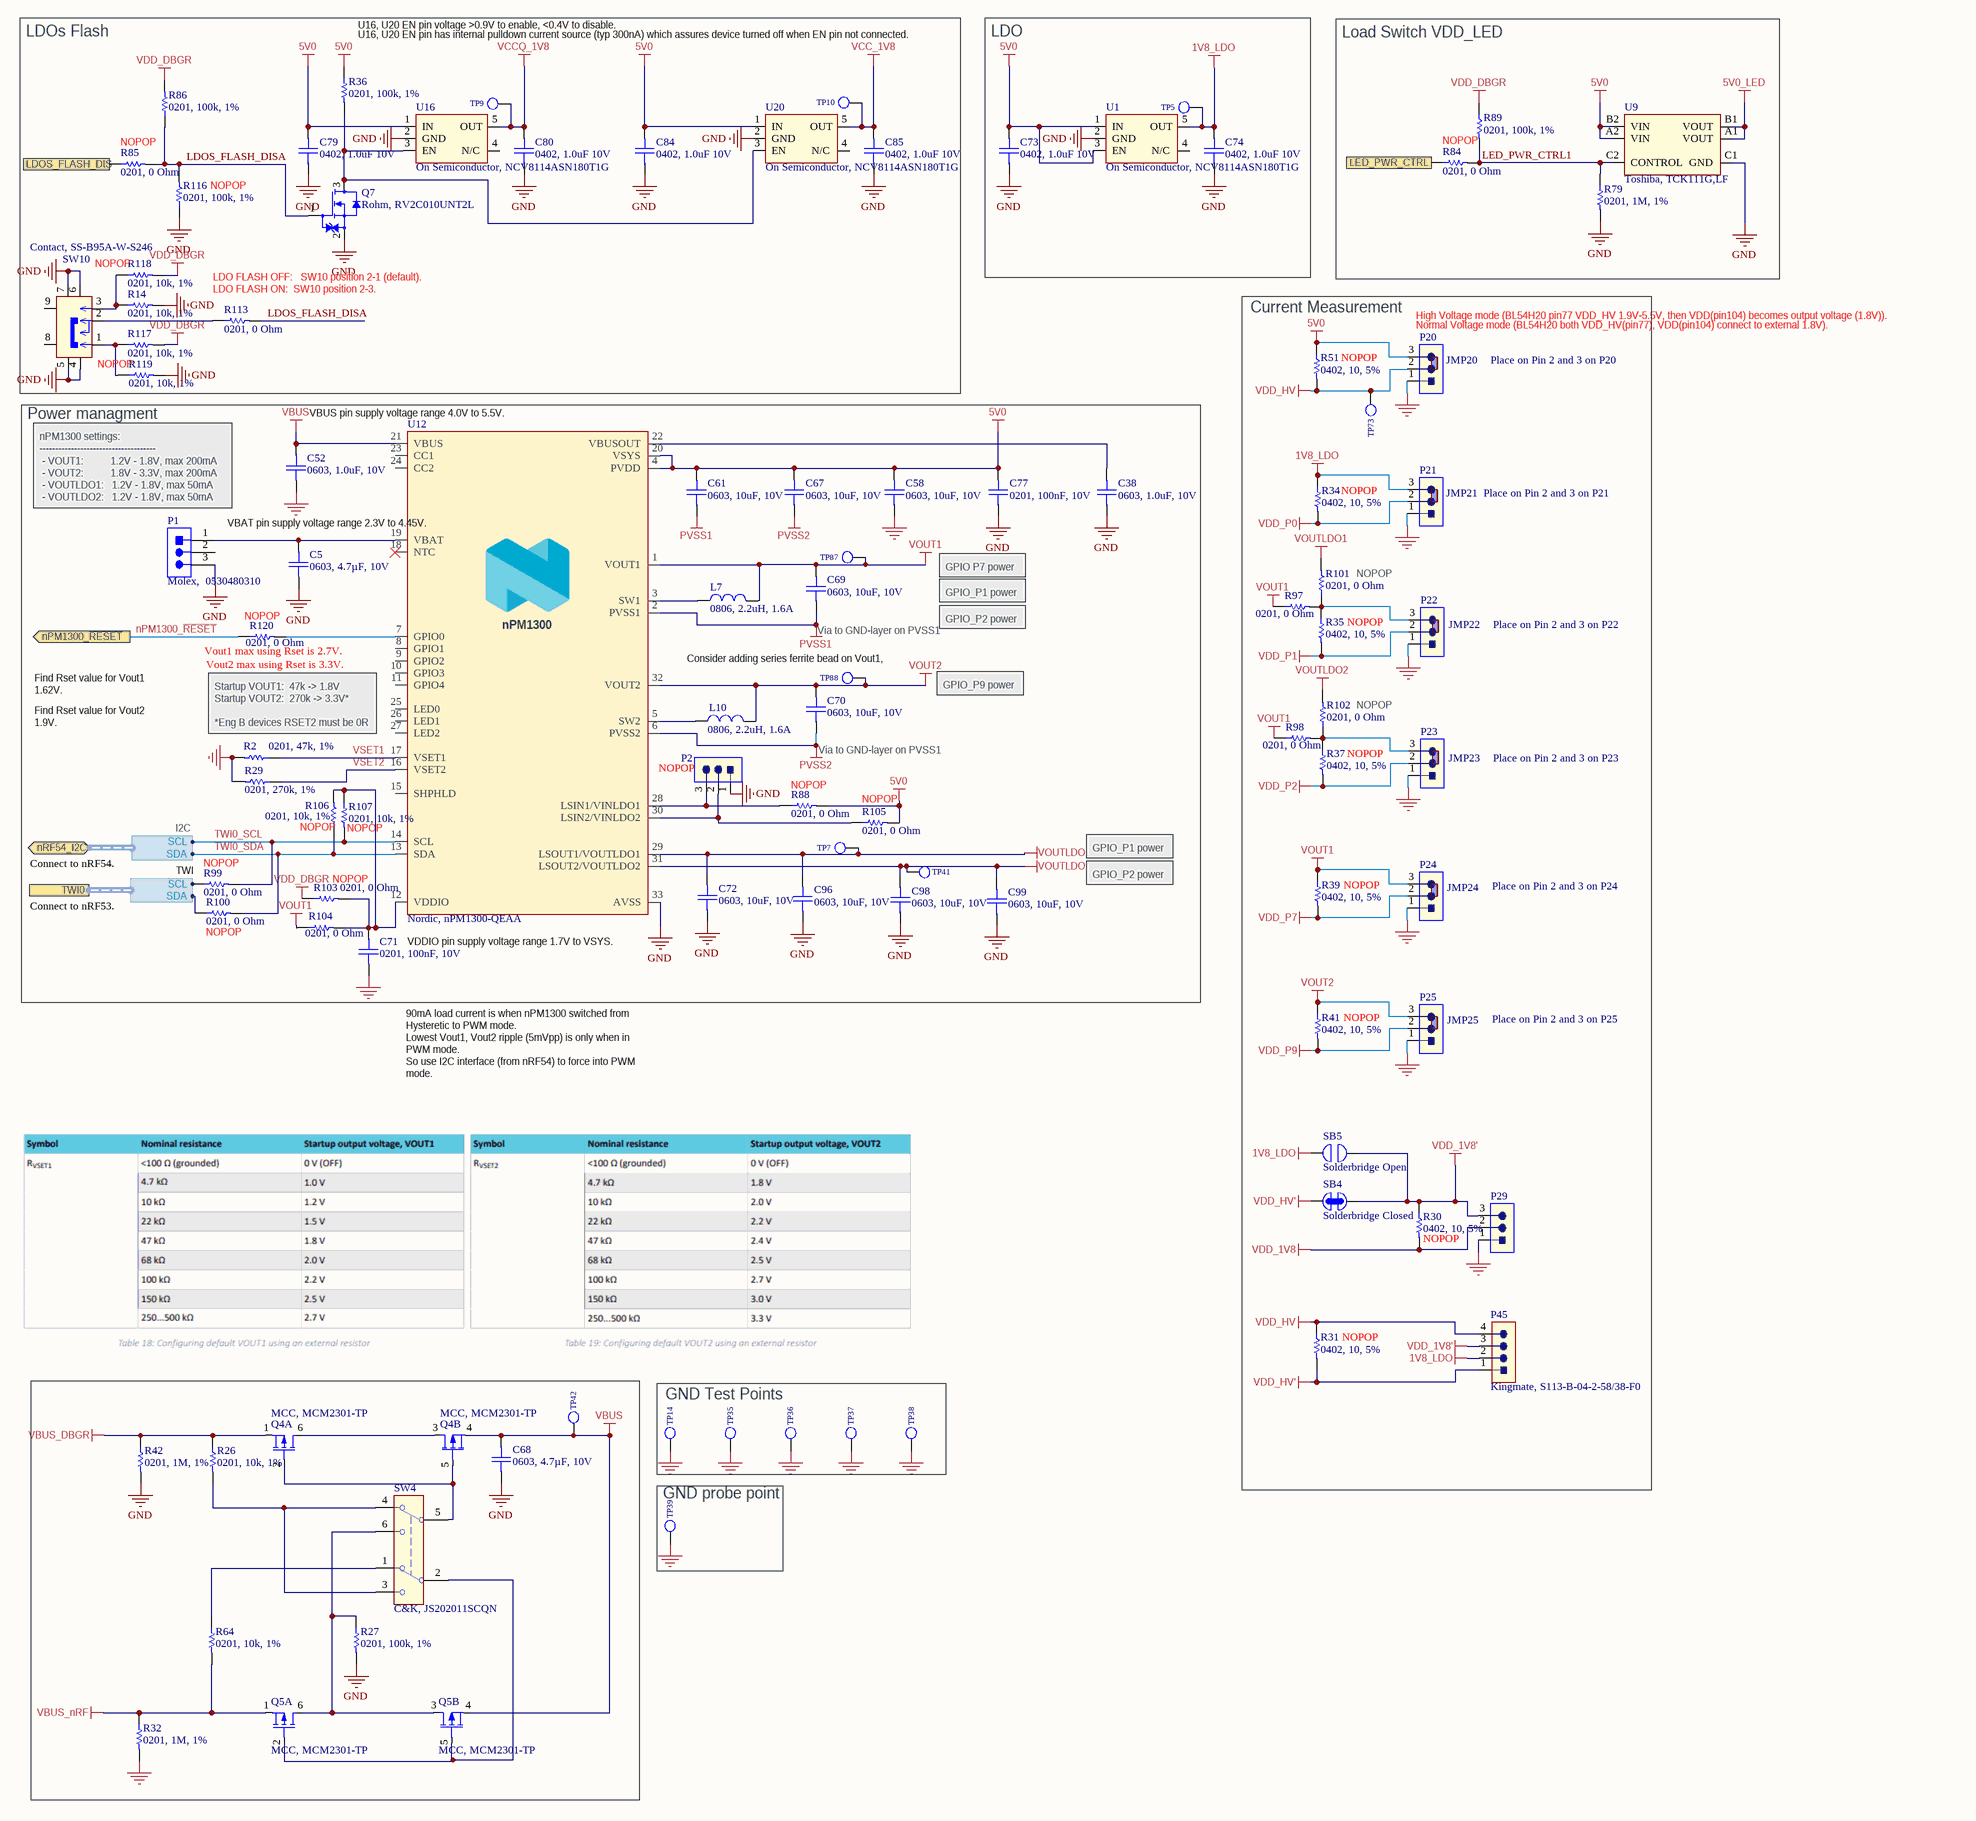
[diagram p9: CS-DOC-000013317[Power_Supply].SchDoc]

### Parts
C5  0603, 4.7µF, 10V  [Chip, 0603, RF]
C38  0603, 1.0uF, 10V  [Chip, 0603, RF]
C52  0603, 1.0uF, 10V  [Chip, 0603, RF]
C58  0603, 10uF, 10V  [Chip, 0603, RF]
C61  0603, 10uF, 10V  [Chip, 0603, RF]
C67  0603, 10uF, 10V  [Chip, 0603, RF]
C68  0603, 4.7µF, 10V  [Chip, 0603, RF]
C69  0603, 10uF, 10V  [Chip, 0603, RF]
C70  0603, 10uF, 10V  [Chip, 0603, RF]
C71  0201, 100nF, 10V  [Cap, C0201, Height 0.3mm]
C72  0603, 10uF, 10V  [Chip, 0603, RF]
C73  0402, 1.0uF 10V  [Chip. 0402, RF]
C74  0402, 1.0uF 10V  [Chip. 0402, RF]
C77  0201, 100nF, 10V  [Cap, C0201, Height 0.3mm]
C79  0402, 1.0uF 10V  [Chip. 0402, RF]
C80  0402, 1.0uF 10V  [Chip. 0402, RF]
C84  0402, 1.0uF 10V  [Chip. 0402, RF]
C85  0402, 1.0uF 10V  [Chip. 0402, RF]
C96  0603, 10uF, 10V  [Chip, 0603, RF]
C98  0603, 10uF, 10V  [Chip, 0603, RF]
C99  0603, 10uF, 10V  [Chip, 0603, RF]
JMP20  Kingmate, S901D-1-1-E1  [Sullins, QPC02SXGN-RC]  (value not drawn)
JMP21  Kingmate, S901D-1-1-E1  [Sullins, QPC02SXGN-RC]  (value not drawn)
JMP22  Kingmate, S901D-1-1-E1  [Sullins, QPC02SXGN-RC]  (value not drawn)
JMP23  Kingmate, S901D-1-1-E1  [Sullins, QPC02SXGN-RC]  (value not drawn)
JMP24  Kingmate, S901D-1-1-E1  [Sullins, QPC02SXGN-RC]  (value not drawn)
JMP25  Kingmate, S901D-1-1-E1  [Sullins, QPC02SXGN-RC]  (value not drawn)
L7  0806, 2.2uH, 1.6A  [IND, 0806, Height 1.0mm]
L10  0806, 2.2uH, 1.6A  [IND, 0806, Height 1.0mm]
P1  Molex,  0530480310  [Molex, 0530480310]
P2  Kingmate, S113-A-03-2-60/33-F0  [2P54MM-1X3, male]  (value not drawn)
P20  Kingmate, S113-A-03-2-60/33-F0  [2P54MM-1X3, male]  (value not drawn)
P21  Kingmate, S113-A-03-2-60/33-F0  [2P54MM-1X3, male]  (value not drawn)
P22  Kingmate, S113-A-03-2-60/33-F0  [2P54MM-1X3, male]  (value not drawn)
P23  Kingmate, S113-A-03-2-60/33-F0  [2P54MM-1X3, male]  (value not drawn)
P24  Kingmate, S113-A-03-2-60/33-F0  [2P54MM-1X3, male]  (value not drawn)
P25  Kingmate, S113-A-03-2-60/33-F0  [2P54MM-1X3, male]  (value not drawn)
P29  Kingmate, S113-A-03-2-60/33-F0  [2P54MM-1X3, male]  (value not drawn)
P45  Kingmate, S113-B-04-2-58/38-F0  [2P54MM-1X4, male]
Q4  MCC, MCM2301-TP  [MCC, MCM2301-TP]  (parts A,B of 2)
Q5  MCC, MCM2301-TP  [MCC, MCM2301-TP]  (parts A,B of 2)
Q7  Rohm, RV2C010UNT2L  [DFN1006-3]
R2  0201, 47k, 1%  [RES, R0201, Height 0.23mm]
R14  0201, 10k, 1%  [RES, R0201, Height 0.23mm]
R26  0201, 10k, 1%  [RES, R0201, Height 0.23mm]
R27  0201, 100k, 1%  [RES, R0201, Height 0.23mm]
R29  0201, 270k, 1%  [RES, R0201, Height 0.23mm]
R30  0402, 10, 5%  [RES, R0402, RF]
R31  0402, 10, 5%  [RES, R0402, RF]
R32  0201, 1M, 1%  [RES, R0201, Height 0.23mm]
R34  0402, 10, 5%  [RES, R0402, RF]
R35  0402, 10, 5%  [RES, R0402, RF]
R36  0201, 100k, 1%  [RES, R0201, Height 0.23mm]
R37  0402, 10, 5%  [RES, R0402, RF]
R39  0402, 10, 5%  [RES, R0402, RF]
R41  0402, 10, 5%  [RES, R0402, RF]
R42  0201, 1M, 1%  [RES, R0201, Height 0.23mm]
R51  0402, 10, 5%  [RES, R0402, RF]
R64  0201, 10k, 1%  [RES, R0201, Height 0.23mm]
R79  0201, 1M, 1%  [RES, R0201, Height 0.23mm]
R84  0201, 0 Ohm  [RES, R0201, Height 0.23mm]
R85  0201, 0 Ohm  [RES, R0201, Height 0.23mm]
R86  0201, 100k, 1%  [RES, R0201, Height 0.23mm]
R88  0201, 0 Ohm  [RES, R0201, Height 0.23mm]
R89  0201, 100k, 1%  [RES, R0201, Height 0.23mm]
R97  0201, 0 Ohm  [RES, R0201, Height 0.23mm]
R98  0201, 0 Ohm  [RES, R0201, Height 0.23mm]
R99  0201, 0 Ohm  [RES, R0201, Height 0.23mm]
R100  0201, 0 Ohm  [RES, R0201, Height 0.23mm]
R101  0201, 0 Ohm  [RES, R0201, Height 0.23mm]
R102  0201, 0 Ohm  [RES, R0201, Height 0.23mm]
R103  0201, 0 Ohm  [RES, R0201, Height 0.23mm]
R104  0201, 0 Ohm  [RES, R0201, Height 0.23mm]
R105  0201, 0 Ohm  [RES, R0201, Height 0.23mm]
R106  0201, 10k, 1%  [RES, R0201, Height 0.23mm]
R107  0201, 10k, 1%  [RES, R0201, Height 0.23mm]
R113  0201, 0 Ohm  [RES, R0201, Height 0.23mm]
R116  0201, 100k, 1%  [RES, R0201, Height 0.23mm]
R117  0201, 10k, 1%  [RES, R0201, Height 0.23mm]
R118  0201, 10k, 1%  [RES, R0201, Height 0.23mm]
R119  0201, 10k, 1%  [RES, R0201, Height 0.23mm]
R120  0201, 0 Ohm  [RES, R0201, Height 0.23mm]
SB4  Solderbridge Closed  [Solder Bridge Closed]  (net tie, no BOM)
SB5  Solderbridge Open  [Solder Bridge Open]  (no BOM)
SW4  C&K, JS202011SCQN  [C&K, JS202011SCQN]
SW10  Contact, SS-B95A-W-S246  [Contact, SS-B95A-W-S246]
TP5  SMT, 1.5mm, Test Pad  [Test Point, SMT 1.5mm Round]  (value not drawn)  (no BOM)
TP7  SMT, 1.5mm, Test Pad  [Test Point, SMT 1.5mm Round]  (value not drawn)  (no BOM)
TP9  SMT, 1.5mm, Test Pad  [Test Point, SMT 1.5mm Round]  (value not drawn)  (no BOM)
TP10  SMT, 1.5mm, Test Pad  [Test Point, SMT 1.5mm Round]  (value not drawn)  (no BOM)
TP14  SMT, 1.5mm, Test Pad  [Test Point, SMT 1.5mm Round]  (value not drawn)  (no BOM)
TP35  SMT, 1.5mm, Test Pad  [Test Point, SMT 1.5mm Round]  (value not drawn)  (no BOM)
TP36  SMT, 1.5mm, Test Pad  [Test Point, SMT 1.5mm Round]  (value not drawn)  (no BOM)
TP37  SMT, 1.5mm, Test Pad  [Test Point, SMT 1.5mm Round]  (value not drawn)  (no BOM)
TP38  SMT, 1.5mm, Test Pad  [Test Point, SMT 1.5mm Round]  (value not drawn)  (no BOM)
TP39  SMT, 1.5mm, Test Pad  [Test Point, SMT 1.5mm Round]  (value not drawn)  (no BOM)
TP41  SMT, 1.5mm, Test Pad  [Test Point, SMT 1.5mm Round]  (value not drawn)  (no BOM)
TP42  SMT, 1.5mm, Test Pad  [Test Point, SMT 1.5mm Round]  (value not drawn)  (no BOM)
TP73  SMT, 1.5mm, Test Pad  [Test Point, SMT 1.5mm Round]  (value not drawn)  (no BOM)
TP87  SMT, 1.5mm, Test Pad  [Test Point, SMT 1.5mm Round]  (value not drawn)  (no BOM)
TP88  SMT, 1.5mm, Test Pad  [Test Point, SMT 1.5mm Round]  (value not drawn)  (no BOM)
U1  On Semiconductor, NCV8114ASN180T1G  [SOT23_5, Height 1.1mm]
U9  Toshiba, TCK111G,LF  [WLCSP-6, 1.0mm x 1.5mm, 0.5mm pitch]
U12  Nordic, nPM1300-QEAA  [QFN32, 5x5, Pitch 0.5mm, Height 1mm]
U16  On Semiconductor, NCV8114ASN180T1G  [SOT23_5, Height 1.1mm]
U20  On Semiconductor, NCV8114ASN180T1G  [SOT23_5, Height 1.1mm]

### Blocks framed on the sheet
LDOs Flash: C79 C80 C84 C85 Q7 R14 R36 R85 R86 R113 R116-R119 SW10 TP9 TP10 U16 U20
LDO: C73 C74 TP5 U1
Load Switch VDD_LED: R79 R84 R89 U9
Current Measurement: JMP20-JMP25 P20-P25 P29 P45 R30 R31 R34 R35 R37 R39 R41 R51 R97 R98 R101 R102 SB4 SB5 TP73
Power managment: C5 C38 C52 C58 C61 C67 C69-C72 C77 C96 C98 C99 L7 L10 P1 P2 R2 R29 R88 R99 R100 R103-R107 R120 TP7 TP41 TP87 TP88 U12
GND Test Points: TP14 TP35-TP38
GND probe point: TP39

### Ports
LDOS_FLASH_DIS (in), LED_PWR_CTRL (in), nPM1300_~{RESET} (out), nRF54_I2C (bidir, harness I2C), TWI0 (harness TWI)

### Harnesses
I2C: SDA, SCL
TWI: SCL, SDA

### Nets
1V8_LDO: C74.2 P21.3 P45.2 R34.1 SB5.2 TP5.1 U1.5(OUT)
5V0: C58.2 C61.2 C67.2 C73.2 C77.2 C79.2 C84.2 P20.3 R36.1 R51.1 R88.2 R105.2 U1.1(IN) U1.3(EN) U9.A2(VIN) U9.B2(VIN) U12.4(PVDD) U12.20(VSYS) U16.1(IN) U20.1(IN)
5V0_LED: U9.A1(VOUT) U9.B1(VOUT)
GND: C5.2 C38.1 C52.2 C58.1 C68.2 C71.2 C72.1 C73.1 C74.1 C77.1 C79.1 C80.1 C84.1 C85.1 C96.1 C98.1 C99.1 P1.3 P2.1 P20.1 P21.1 P22.1 P23.1 P24.1 P25.1 P29.1 Q7.2(S) R2.2 R14.2 R27.2 R29.2 R32.2 R42.2 R79.2 R116.1 R119.2 SW10.4 SW10.5 SW10.6 SW10.7 TP14.1 TP35.1 TP36.1 TP37.1 TP38.1 TP39.1 U1.2(GND) U9.C1(GND) U12.33(AVSS) U16.2(GND) U20.2(GND)
PVSS1: C61.1 C69.1 U12.2(PVSS1)
PVSS2: C67.1 C70.1 U12.6(PVSS2)
VBUS: C52.1 C68.1 Q4.4(S2) Q5.4(S2) TP42.1 U12.21(VBUS)
VBUS_DBGR: Q4.1(S1) R26.1 R42.1
VBUS_nRF: Q5.1(S1) R32.1 R64.2
VCC_1V8: C85.2 TP10.1 U20.5(OUT)
VCCQ_1V8: C80.2 TP9.1 U16.5(OUT)
VDD_1V8: P29.2 R30.2
VDD_1V8': P29.3 P45.3 R30.1 SB4.1 SB5.1
VDD_DBGR: R86.2 R89.1 R103.1 R117.2 R118.2
VDD_HV: P20.2 P45.4 R31.1 R51.2 TP73.1
VDD_HV': P45.1 R31.2 SB4.2
VDD_P0: P21.2 R34.2
VDD_P1: P22.2 R35.2
VDD_P2: P23.2 R37.2
VDD_P7: P24.2 R39.2
VDD_P9: P25.2 R41.2
VOUT1: C69.2 L7.1 P24.3 R39.1 R97.1 R98.1 R104.1 TP87.1 U12.1(VOUT1)
VOUT2: C70.2 L10.1 P25.3 R41.1 TP88.1 U12.32(VOUT2)
VOUTLDO1: C72.2 C96.2 R101.2 TP7.1 U12.29(LSOUT1/VOUTLDO1)
VOUTLDO2: C98.2 C99.2 R102.2 TP41.1 U12.31(LSOUT2/VOUTLDO2)
LDOS_FLASH_DIS: R85.1 ; port LDOS_FLASH_DIS
LDOS_FLASH_DISA: Q7.1(G) R85.2 R86.1 R113.2 R116.2
LED_PWR_CTRL: R84.1 ; port LED_PWR_CTRL
LED_PWR_CTRL1: R79.1 R84.2 R89.2 U9.C2(CONTROL)
nPM1300_~{RESET}: R120.1 ; port nPM1300_~{RESET}
TWI0_SCL: R99.2 R107.2 U12.14(SCL) ; port nRF54_I2C.SCL  [project net P1.03]
TWI0_SCL: R99.1 ; port TWI0.SCL  [a separate net that carries the same name]
TWI0_SDA: R100.2 R106.1 U12.13(SDA) ; port nRF54_I2C.SDA  [project net P1.04]
TWI0_SDA: R100.1 ; port TWI0.SDA  [a separate net that carries the same name]
VSET1: R2.1 U12.17(VSET1)
VSET2: R29.1 U12.16(VSET2)
NetC5_1: C5.1 P1.1 U12.19(VBAT)
NetC38_2: C38.2 U12.22(VBUSOUT)
NetC71_1: C71.1 R103.2 R104.2 R106.2 R107.1 U12.12(VDDIO)
NetL7_2: L7.2 U12.3(SW1)
NetL10_2: L10.2 U12.5(SW2)
NetP2_2: P2.2 R105.1 U12.30(LSIN2/VINLDO2)
NetP2_3: P2.3 R88.1 U12.28(LSIN1/VINLDO1)
NetP22_3: P22.3 R35.1 R97.2 R101.1
NetP23_3: P23.3 R37.1 R98.2 R102.1
NetQ4_2: Q4.2(G1) Q4.5(G2) SW4.5
NetQ4_3: Q4.3(D2) Q4.6(D1)
NetQ5_2: Q5.2(G1) Q5.5(G2) SW4.2
NetQ5_3: Q5.3(D2) Q5.6(D1) R27.1 SW4.6
NetQ7_3: Q7.3(D) R36.2 U16.3(EN) U20.3(EN)
NetR14_1: R14.1 R118.1 SW10.3
NetR26_2: R26.2 SW4.3 SW4.4
NetR64_1: R64.1 SW4.1
NetR113_1: R113.1 SW10.2
NetR117_1: R117.1 R119.1 SW10.1
NetR120_2: R120.2 U12.7(GPIO0)

Not connected (* = marked no-connect by the designer): P1 2; SW10 8 9; U1 4(N/C); U12 8(GPIO1) 9(GPIO2) 10(GPIO3) 11(GPIO4) 15(SHPHLD) 18(NTC)* 23(CC1) 24(CC2) 25(LED0) 26(LED1) 27(LED2); U16 4(N/C); U20 4(N/C)

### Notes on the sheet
- U16, U20 EN pin voltage >0.9V to enable, <0.4V to disable.
- U16, U20 EN pin has internal pulldown current source (typ 300nA) which assures device turned off when EN pin not connected.
- (near R85) NOPOP
- (near R116) NOPOP
- NOPOP
- (near R118) NOPOP
- (near R113) LDO FLASH ON:  SW10 position 2-3.
- LDO FLASH OFF:   SW10 position 2-1 (default).
- High Voltage mode (BL54H20 pin77 VDD_HV 1.9V-5.5V, then VDD(pin104) becomes output voltage (1.8V)).
- Normal Voltage mode (BL54H20 both VDD_HV(pin77), VDD(pin104) connect to external 1.8V).
- Place on Pin 2 and 3 on P20
- VBUS pin supply voltage range 4.0V to 5.5V.
- nPM1300 settings:
  -------------------------------------
  - VOUT1:          1.2V - 1.8V, max 200mA
  - VOUT2:          1.8V - 3.3V, max 200mA
  - VOUTLDO1:   1.2V - 1.8V, max 50mA
  - VOUTLDO2:   1.2V - 1.8V, max 50mA
- (near U12) VBAT pin supply voltage range 2.3V to 4.45V.
- (near R34) NOPOP
- (near JMP21) Place on Pin 2 and 3 on P21
- GPIO P7 power
- GPIO_P1 power
- (near R120) Vout1 max using Rset is 2.7V.
- (near R120) Vout2 max using Rset is 3.3V.
- (near R120) NOPOP
- (near TP88) Consider adding series ferrite bead on Vout1, Vout2.
- Via to GND-layer on PVSS1
- GPIO_P2 power
- Place on Pin 2 and 3 on P22
- Find Rset value for Vout1 1.62V.
  Find Rset value for Vout1 1.98V.
- Find Rset value for Vout2 1.9V.
  Find Rset value for Vout2 3.3V.
- Startup VOUT1:  47k -> 1.8V
  Startup VOUT2:  270k -> 3.3V*
  *Eng B devices RSET2 must be 0R
- GPIO_P9 power
- (near U12) NOPOP
- (near R88) NOPOP
- (near C70) Via to GND-layer on PVSS1
- Place on Pin 2 and 3 on P23
- (near R106) NOPOP
- (near R107) NOPOP
- (near R105) NOPOP
- Connect to nRF54.
- Connect to nRF53.
- (near R99) NOPOP
- (near R103) NOPOP
- (near R39) NOPOP
- Place on Pin 2 and 3 on P24
- (near R100) NOPOP
- VDDIO pin supply voltage range 1.7V to VSYS.
- (near R41) NOPOP
- Place on Pin 2 and 3 on P25
- 90mA load current is when nPM1300 switched from
  Hysteretic to PWM mode.
  Lowest Vout1, Vout2 ripple (5mVpp) is only when in PWM mode.
  So use I2C interface (from nRF54) to force into PWM mode.
  Lowest ripple needed for nRF54 radio.
- (near R30) NOPOP
- (near R31) NOPOP

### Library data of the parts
C5 C68 = CMP-CAP-502-00117-1.11: CAP, SMT, 0603, MLCC, 4.7µF, 10V, X7S, 10%,; Manufacturer: Murata; Manufacturer Part Number: GRM188C71A475KE11D; Value: 4.7uF; Substitutes Allowed: NO
C38 C52 = CMP-CAP-502-00046-1.12: CAP, SMT, 0603, MLCC, 1.0uF, 10V, X7R, 10%,; Manufacturer: Murata; Manufacturer Part Number: GRM188R71A105KA61D; Substitutes Allowed: NO
C58 C61 C67 C69 C70 C72 C96 C98 C99 = CMP-CAP-502-00414-1.2: CAP, SMT, 0603, MLCC, 10uF, 10V, X6S, 10%; Manufacturer: Murata; Manufacturer Part Number: GRM188C81A106KA73#; Substitutes Allowed: NO
C71 = CMP-CAP-502-00106-1.11: as C13 on sheet CS-DOC-000013317[Debugger_MCU]
C73 C74 C79 C80 C84 C85 = CMP-CAP-502-00101-1.17: CAP, SMT, 0402, MLCC, 1.0uF, 10V, X7S, 10%; Manufacturer: Murata; Manufacturer Part Number: GRM155C71A105KE11#; Substitutes Allowed: NO
C77 = CMP-CAP-502-00106-1.11: as C41 on sheet CS-DOC-000013317[Level_Shifters]
JMP20-JMP25 = CMP-CON-130-00121-1.11: CON, TH, Pin header jumper CAP open type, Pitch 2.54mm,; Alt. Manufacturer: Any; Rows: 1; Substitutes Allowed: YES
L7 L10 = CMP-IND-511-00164-1.1: IND, SMT, 0806, Power Inductor, 2.2uH, 1.6A, 20%, 1MHz, 135 mOhm; Manufacturer: Wurth Elektronik; Manufacturer Part Number: 74479276222C; SRF: 40 MHz; Substitutes Allowed: NO
P1 = CMP-CON-130-00030-1.8: CON, TH, Header, 1x3, 1.25mm,; Substitutes Allowed: NO; Rows: 1; Voltage: 125VAC/DC
P2 P20-P25 P29 = CMP-CON-130-00220-1.3: CON, SMT, Header, 1X3 pins, 2.54mm pitch, Male, Vertical; Rows: 1; Substitutes Allowed: NO
P45 = CMP-CON-130-00242-1.0: CON, SMT, Header, 1X4 pins, 2.54mm pitch, Male, Vertical; Rows: 1
Q4 Q5 = CMP-FET-506-00031-1.0: FET, SMT, DFN2020-6, Dual P-Channel, 20V, 3.8A, 90 mOhm, 0.9Vgs max; Manufacturer: Micro Commercial Components; Vgs On: 0.9V; Rds On (Max): 90 mOhm; Power Max (W): 1.4W; Substitutes Allowed: NO
Q7 = CMP-FET-506-00027-1.2: as Q6 on sheet CS-DOC-000013317[Level_Shifters]
R2 = CMP-RES-514-00260-1.1: RES, SMT, 0201, Thick Film, 47k, 1%, 0.05W; Manufacturer Part Number: RC0201FR-0747KL; Alt. Manufacturer Part Number: Any; Manufacturer: Yageo; Substitutes Allowed: YES
R14 R26 R64 R106 R107 R117-R119 = CMP-RES-514-00247-1.2: as R12 on sheet CS-DOC-000013317[Level_Shifters]
R27 R36 R89 = CMP-RES-514-00064-1.24: as R6 on sheet CS-DOC-000013317[Debugger_MCU]
R29 = CMP-RES-514-00326-1.1: RES, SMT, 0201, Thick Film, 270k, 1%, 0.05W, 25V; Alt. Manufacturer Part Number: Any; Manufacturer Part Number: RC0201FR-07270KL; Manufacturer: Yageo; Substitutes Allowed: YES
R30 R31 R34 R35 R37 R39 R41 R51 = CMP-RES-514-00140-1.10: RES, SMT, 0402, Thick Film, 10, 5%, 0.0625W; Alt. Manufacturer Part Number: Any; Manufacturer: Yageo; Manufacturer Part Number: RC0402JR-0710RL; Substitutes Allowed: YES; Value: 10
R32 R42 R79 = CMP-RES-514-00017-1.28: RES, SMT, 0201, Thick Film, 1M, 1%, 0.05W; Manufacturer: Yageo; Alt. Manufacturer Part Number: Any; Manufacturer Part Number: RC0201FR-071ML; Substitutes Allowed: YES
R84 R85 R88 R97-R105 R113 R120 = CMP-RES-514-00004-1.31: as R50 on sheet CS-DOC-000013317[Level_Shifters]
R86 R116 = CMP-RES-514-00064-1.24: as R8 on sheet CS-DOC-000013317[Debugger_MCU]
SB4 = CMP-Misc-522-00004-1.17: MSC, Solderbridge Closed
SB5 = CMP-Misc-522-00003-1.9: MSC, Solderbridge Open
SW4 = CMP-SW-516-00040-1.0: SW, SMD, Slide, DPDT, On, On, 6VDC, 300mA; Switch Function: (On, On); Substitutes Allowed: NO; Voltage Rating AC/DC: 6V
SW10 = CMP-SW-516-00015-1.3: as SW7 on sheet CS-DOC-000013317[Level_Shifters]
TP5 TP7 TP9 TP10 TP14 TP35-TP39 TP41 TP42 TP73 TP87 TP88 = CMP-MSC-522-00070-1.0: MSC, SMT, 1.5mm, Test Pad
U1 U16 U20 = CMP-IC-510-00397-1.1: IC, SMT, 5-TSOP, LDO Voltage Regulators, 300mA, 1.8V; Substitutes Allowed: NO
U9 = CMP-IC-510-00341-1.1: IC, SMT, SOT25, 1.0x1.5mm, Power Switch/Driver 1:1 N-Channel, 1.1V~5.5V, 3A; Subpart Type: Load Switch; Substitutes Allowed: NO
U12 = CMP-IC-510-00351-1.4: IC, SMT, QFN32, PMIC, 4V~5.5V; Manufacturer: Nordic Semiconductor; Substitutes Allowed: NO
